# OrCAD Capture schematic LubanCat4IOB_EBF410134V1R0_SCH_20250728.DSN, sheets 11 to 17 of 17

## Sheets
11 14 MIPI CSI PORT: size A3; note: MIPI CSI PORT
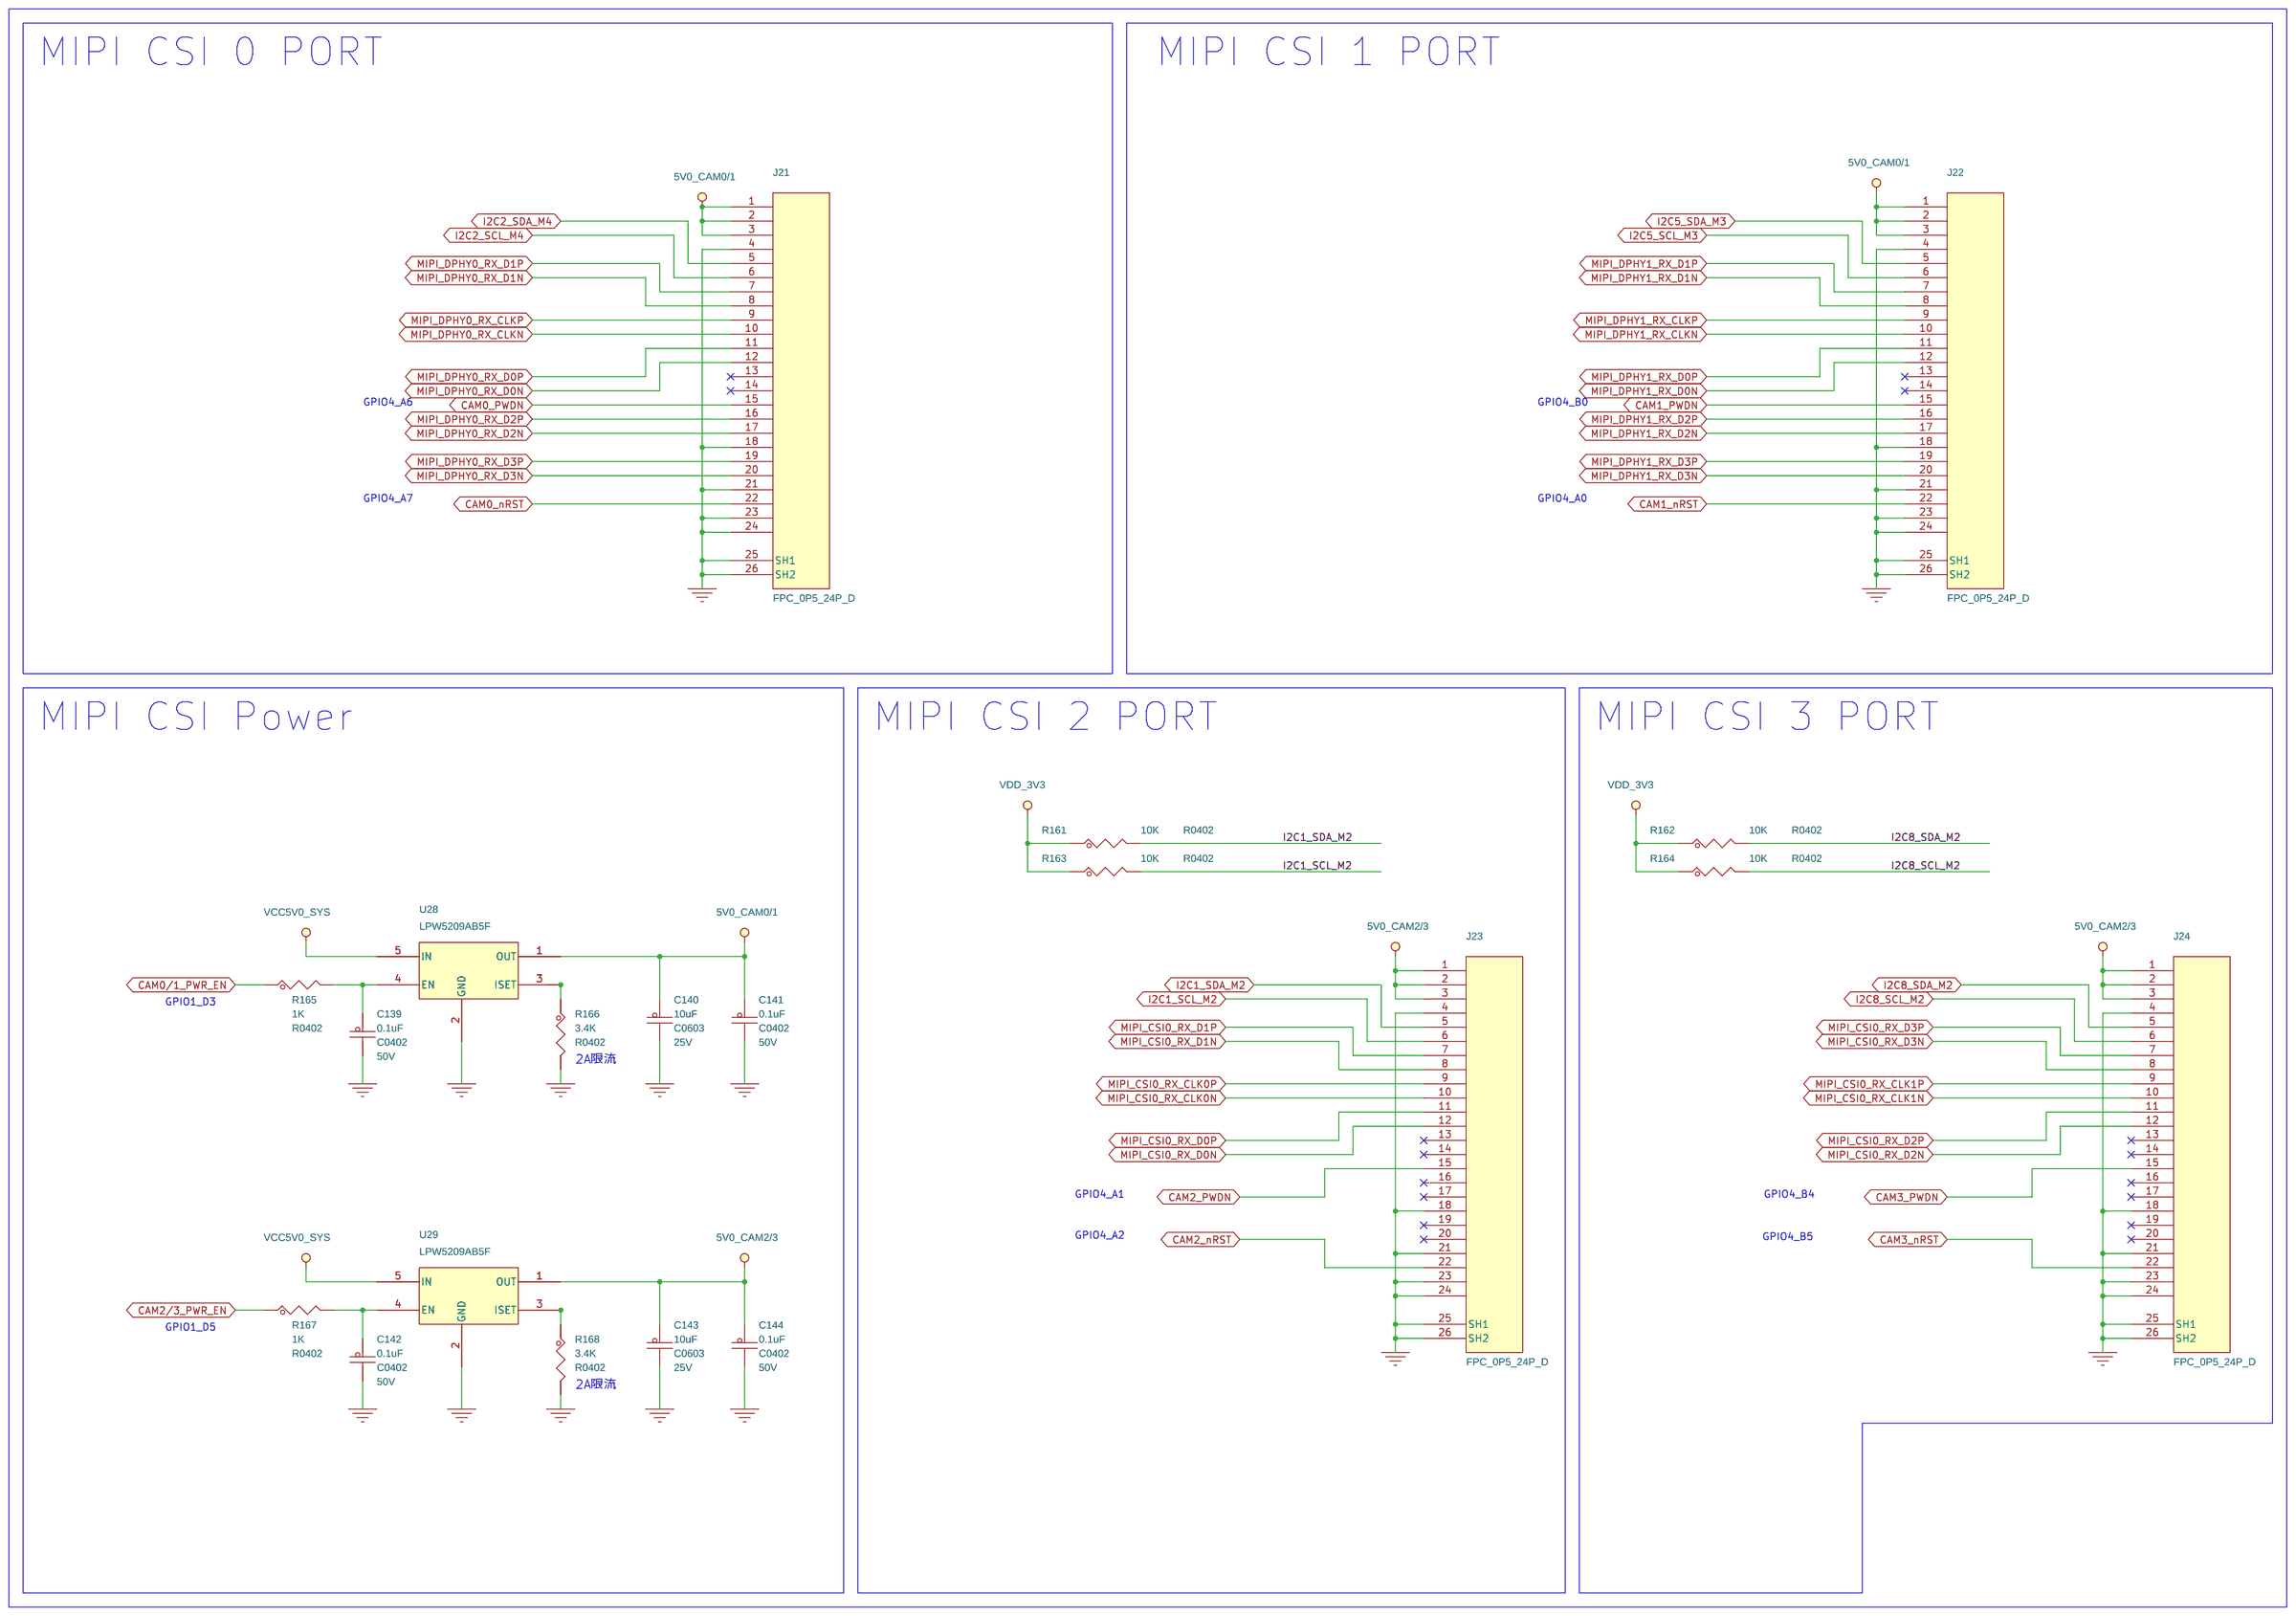
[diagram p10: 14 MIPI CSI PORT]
12 15 MINI PCIE_PORT: size A3; note: MINI PCIE PORT
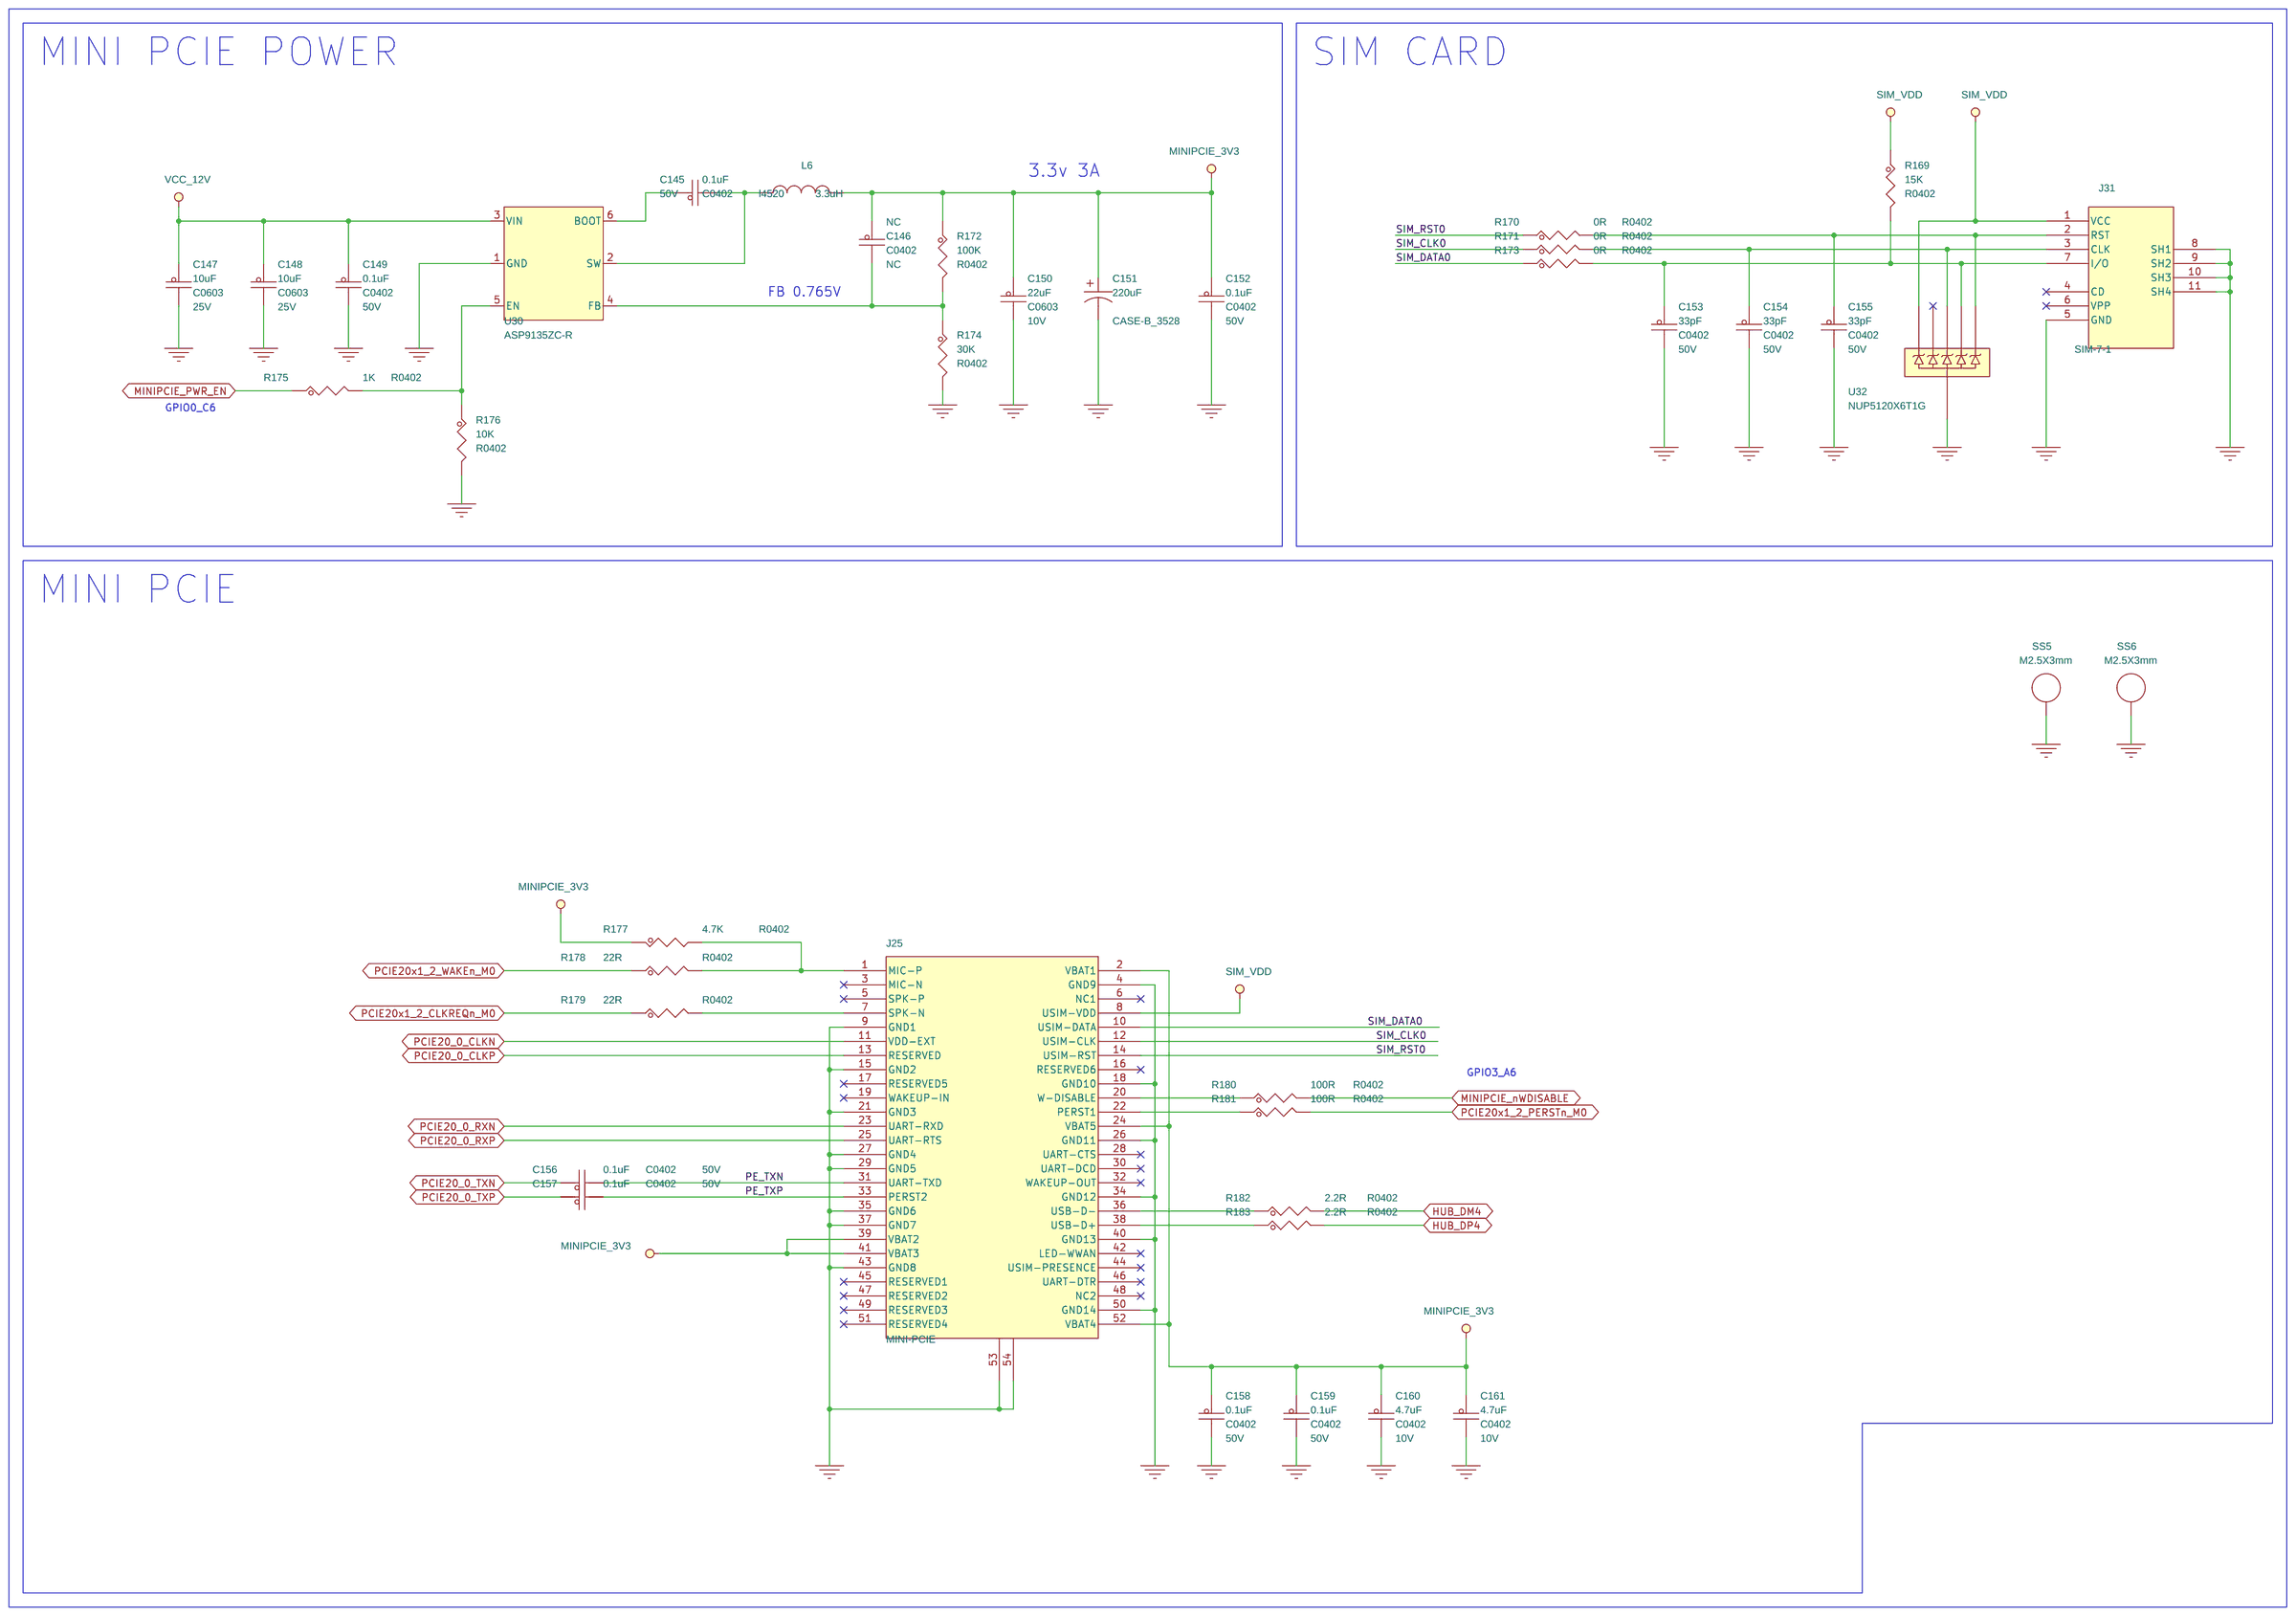
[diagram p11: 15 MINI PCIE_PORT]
13 16 AUDIO PORT: size A3; note: AUDIO PORT
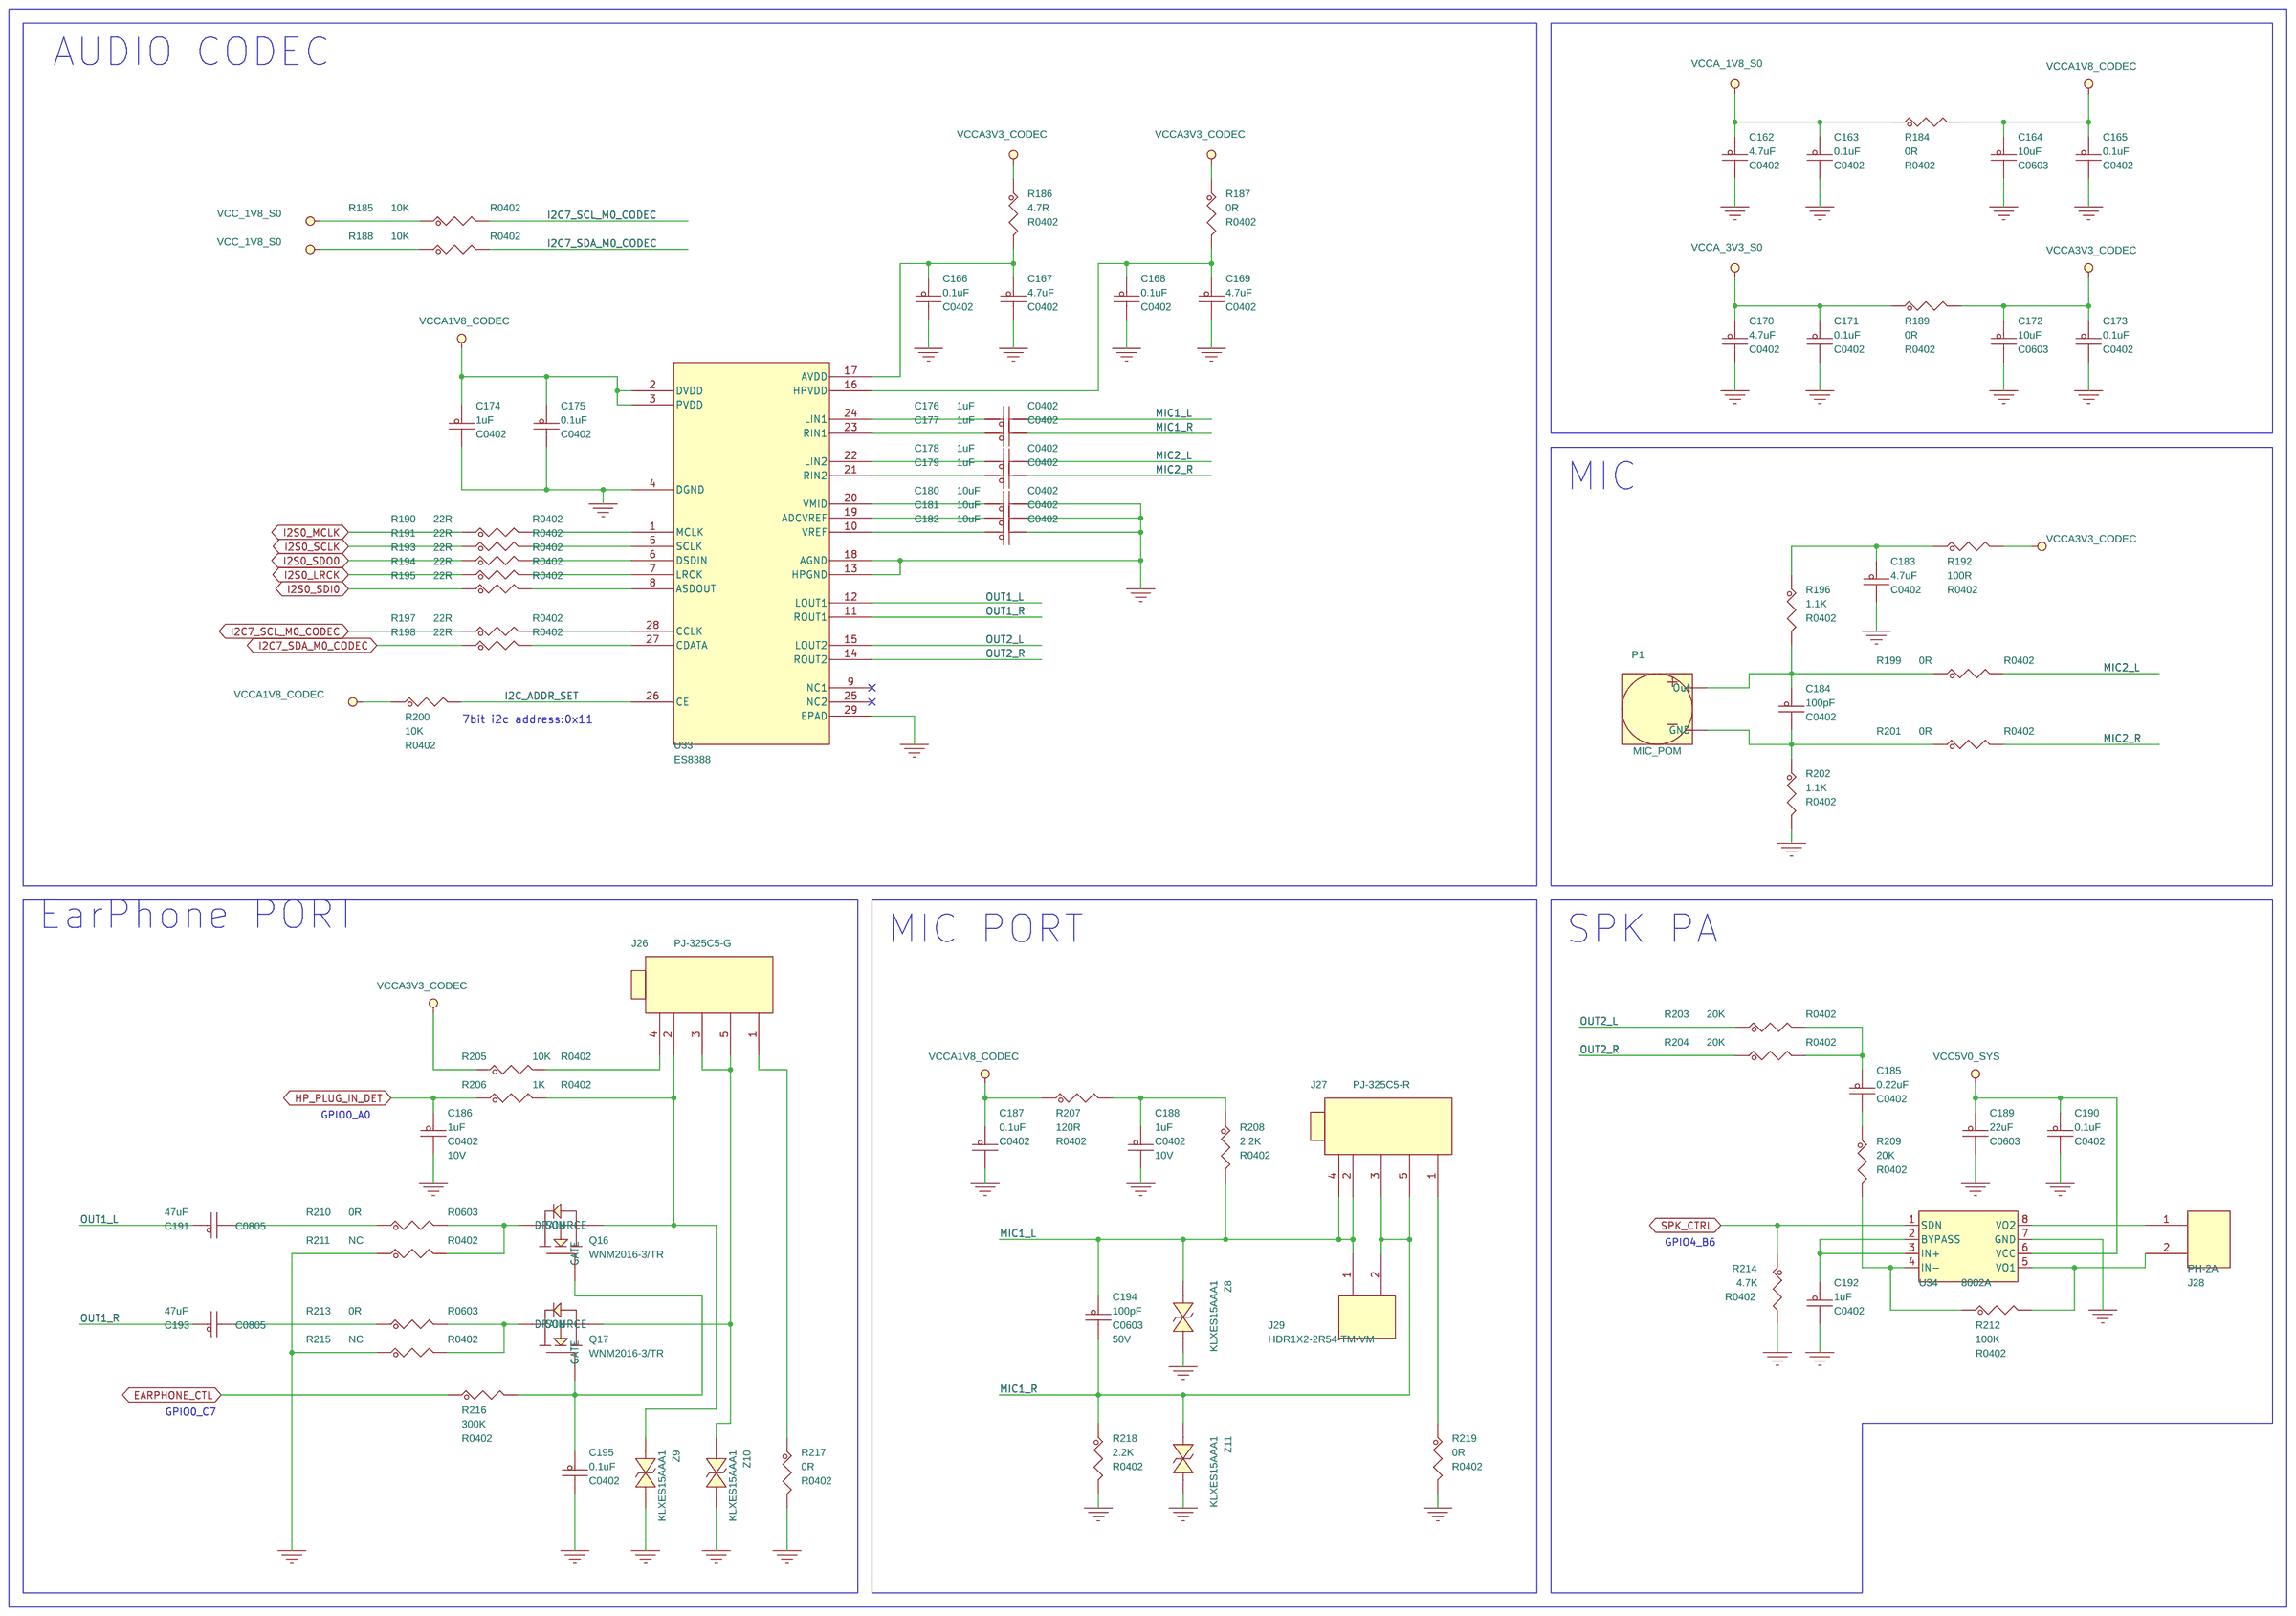
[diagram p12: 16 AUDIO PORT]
14 07 SD/RS232/RTC: size A3; note: RTC/SD/RS232
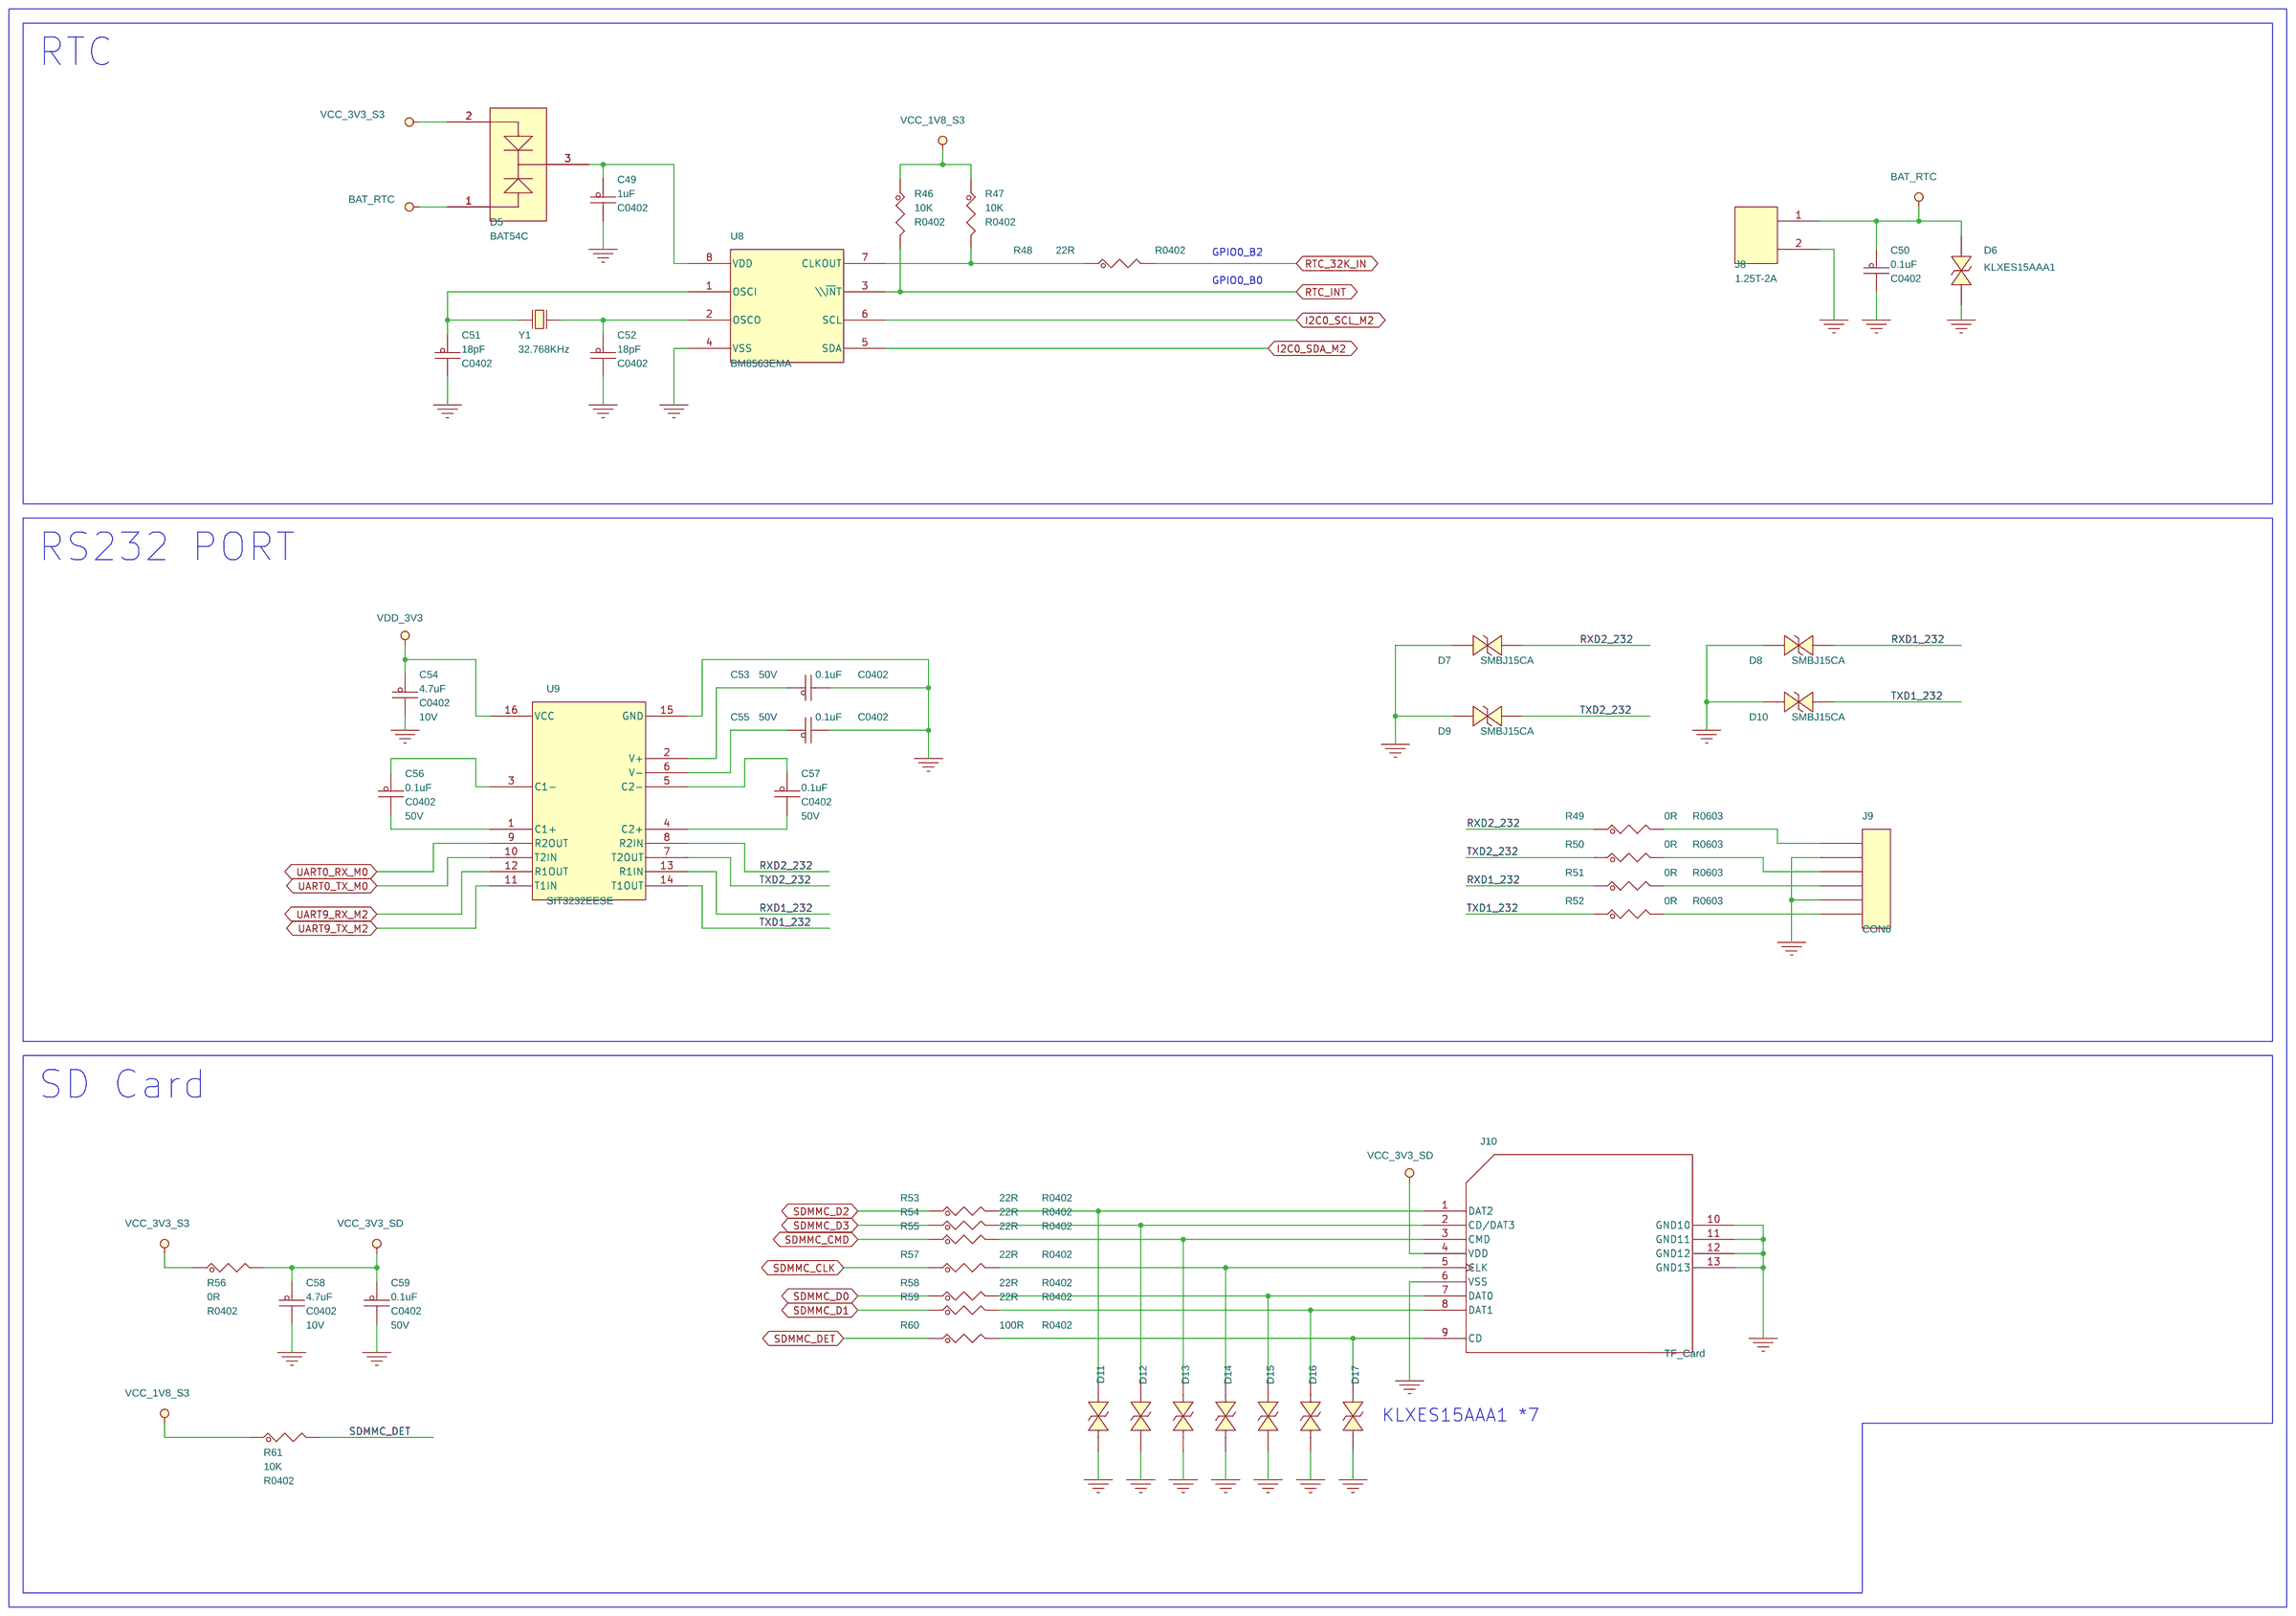
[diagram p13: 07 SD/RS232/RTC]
15 08 RS485/CAN PORT: size A3; note: RS485/CAN PORT
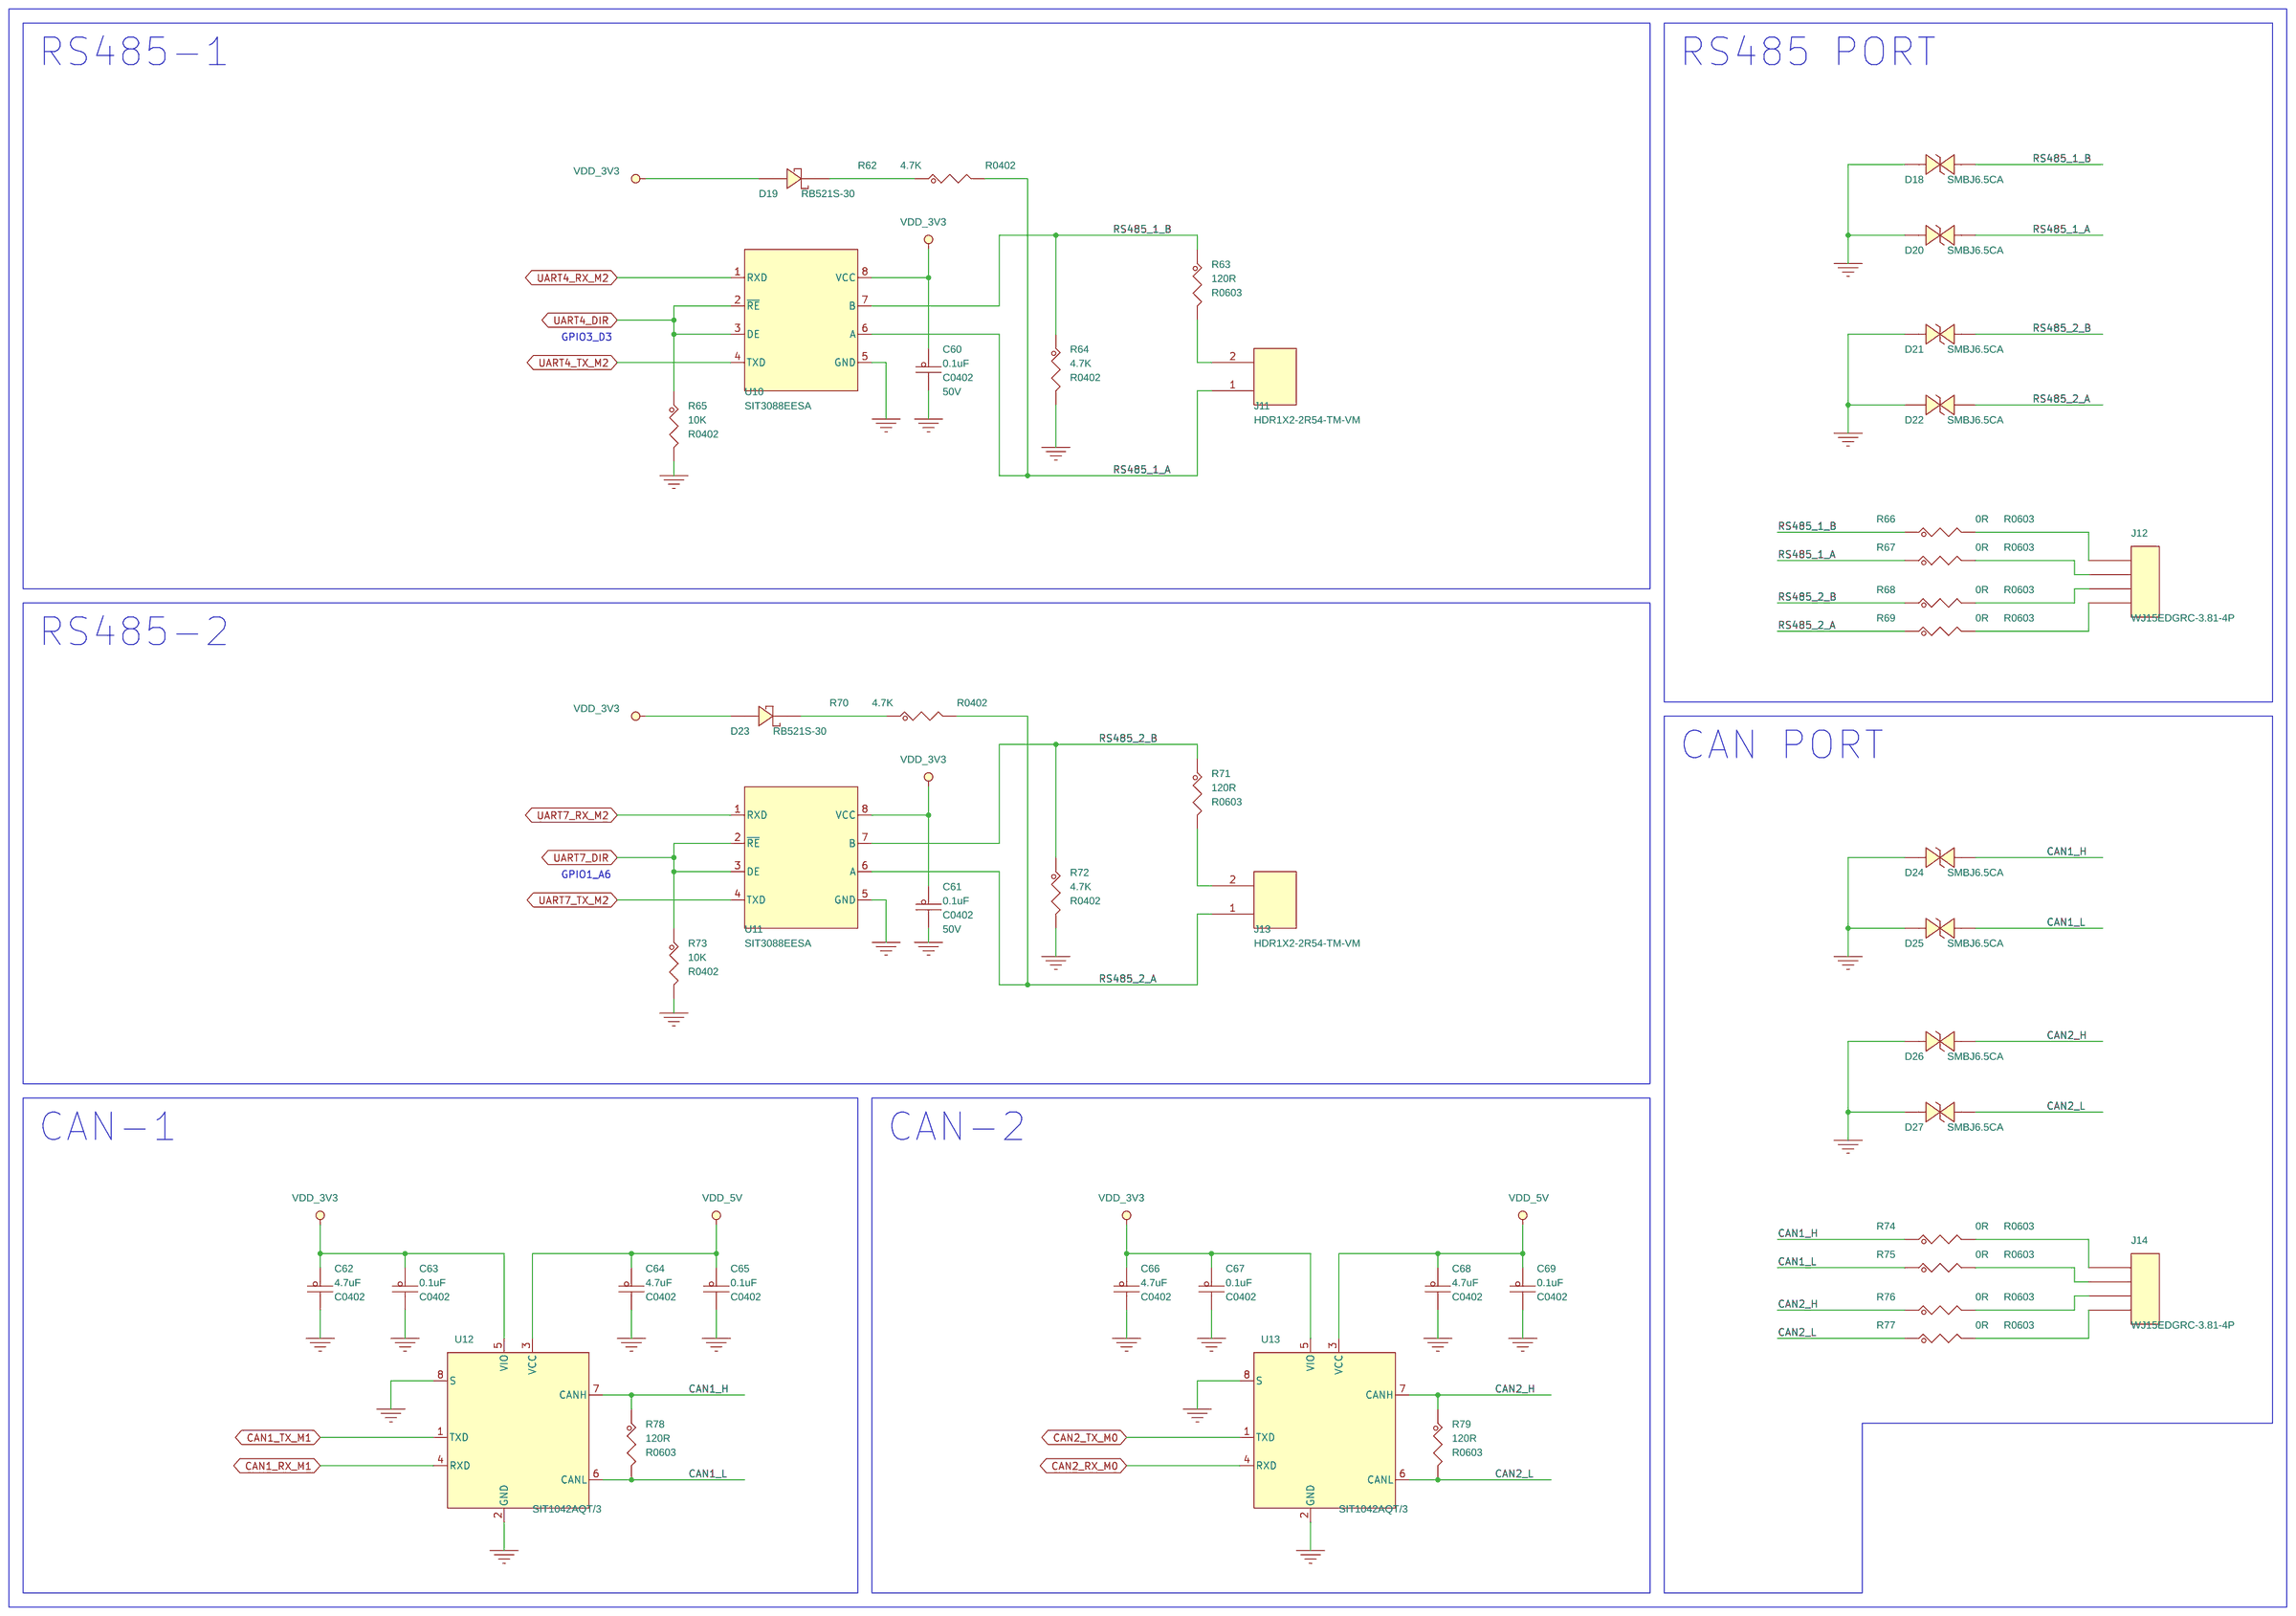
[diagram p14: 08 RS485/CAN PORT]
16 04 DC IN/POWER/FAN: size A3; note: DC IN/POWER/FAN
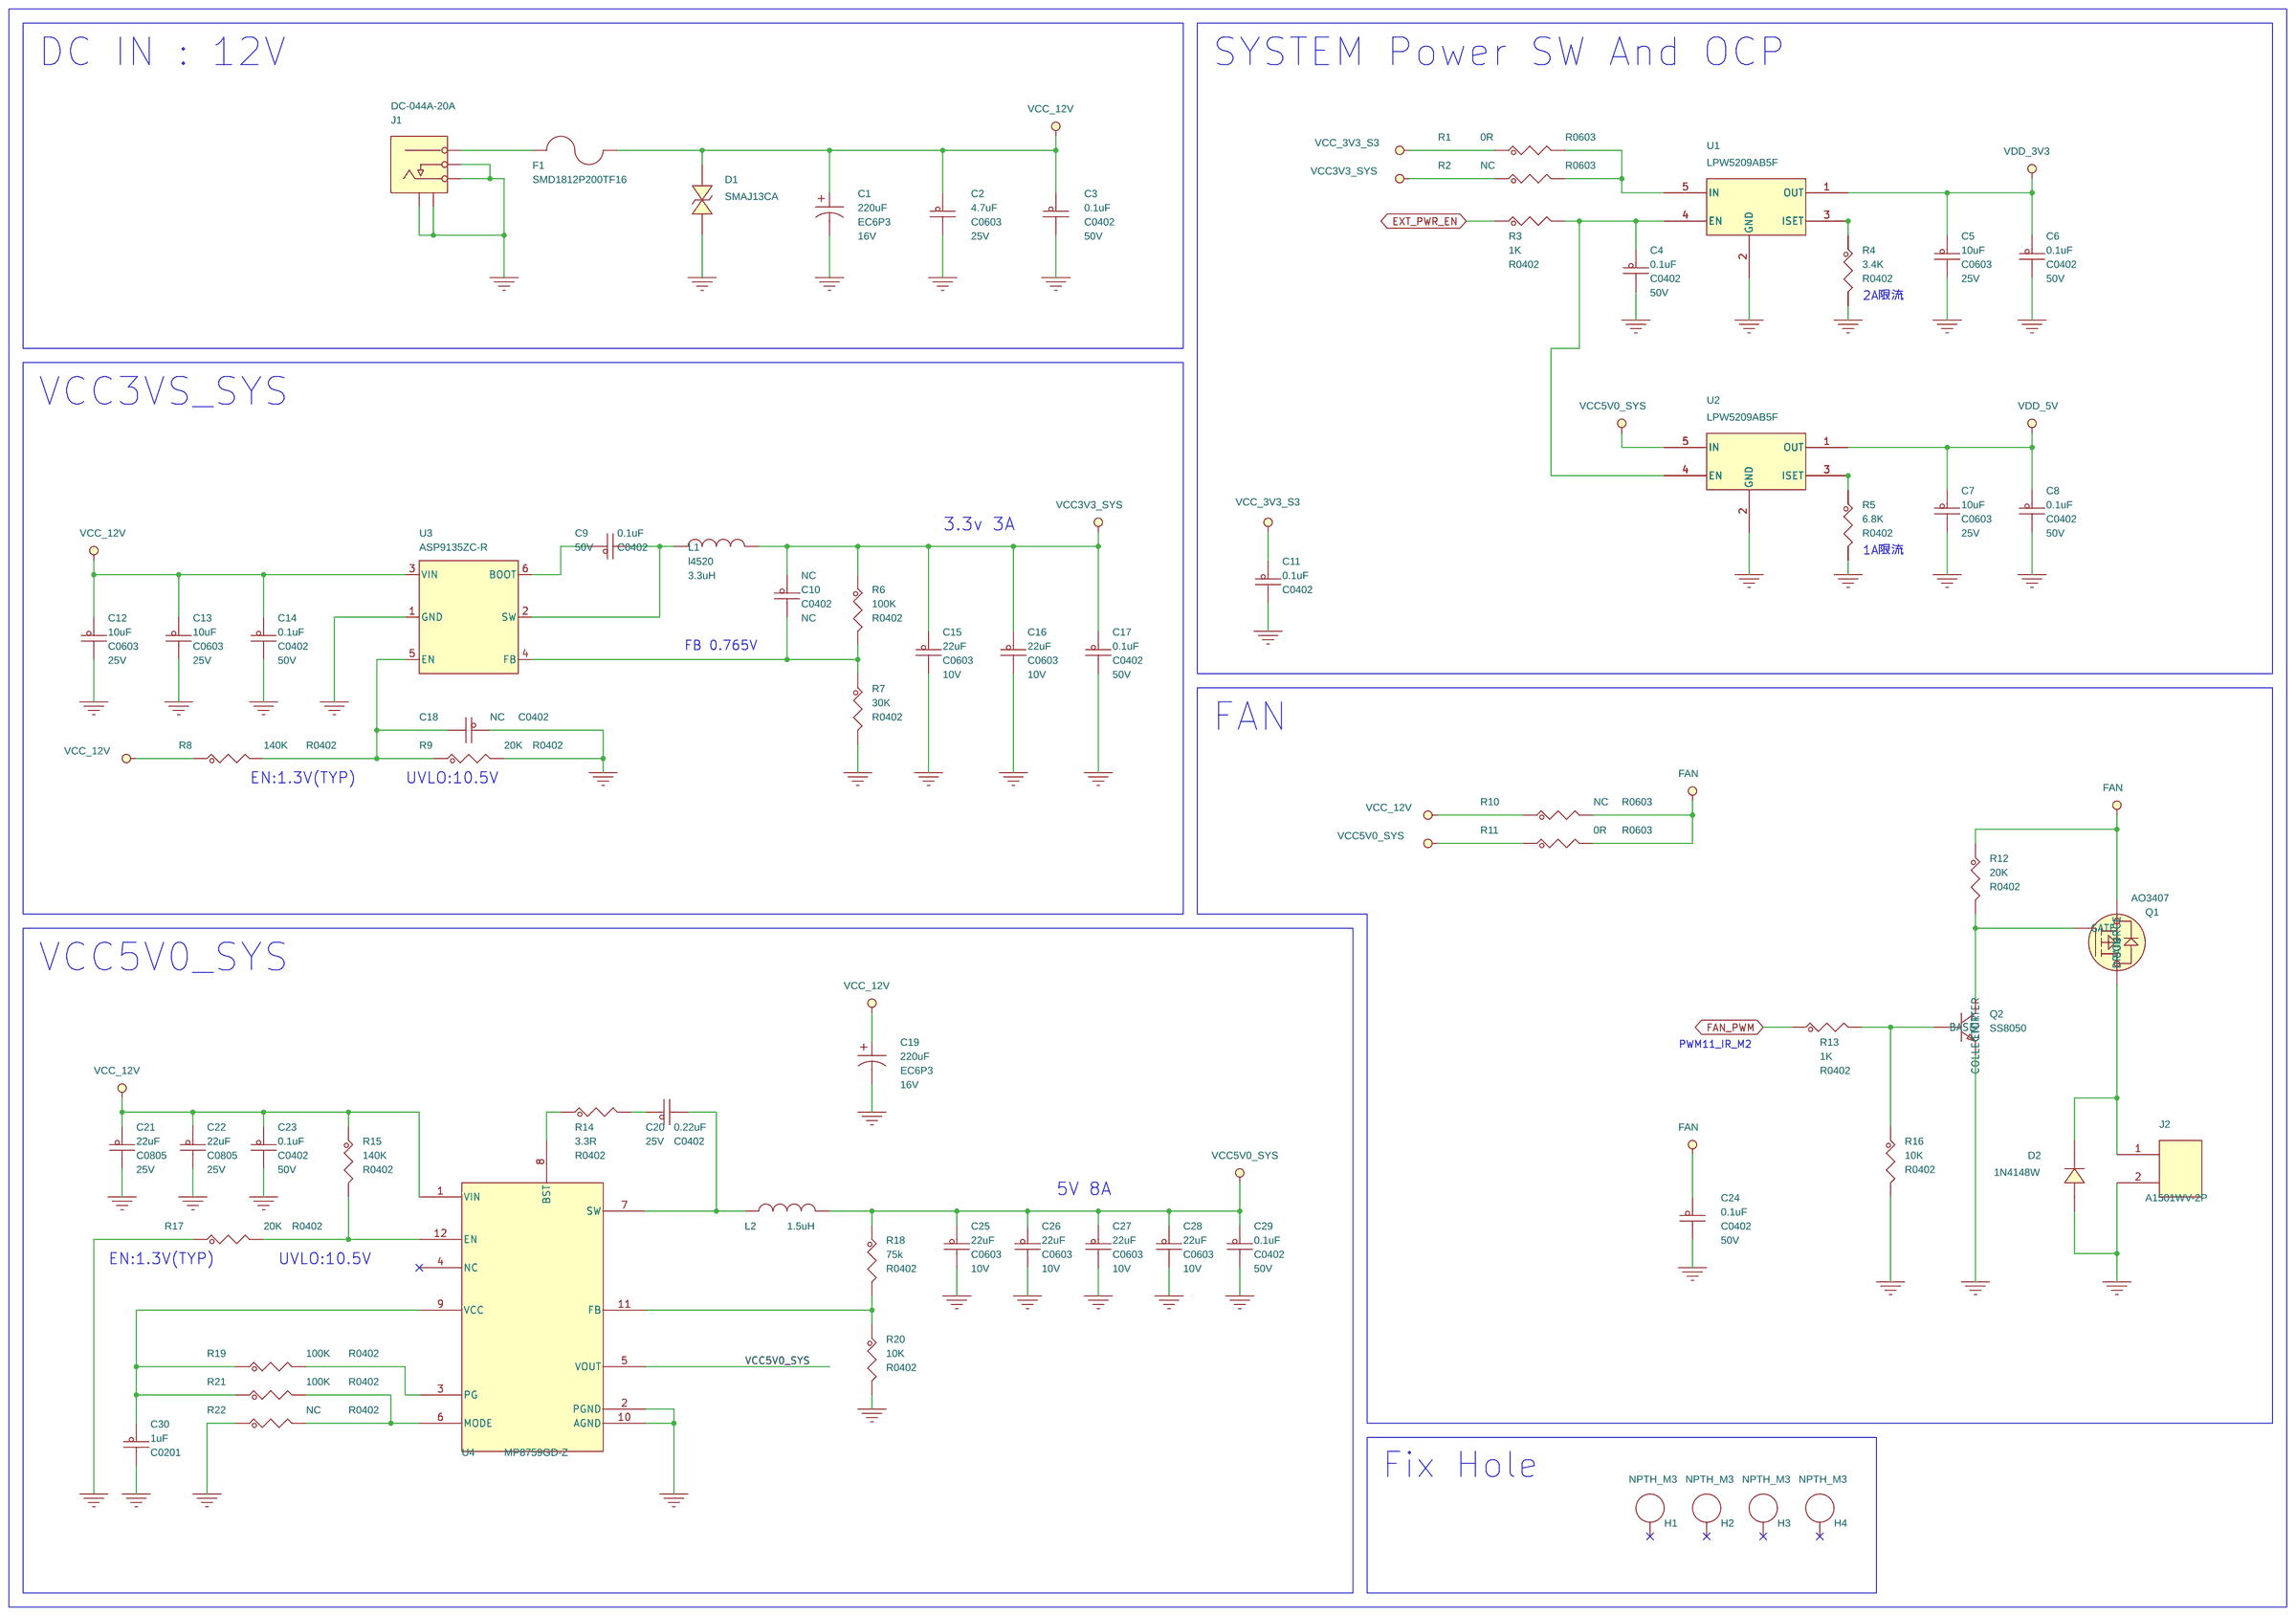
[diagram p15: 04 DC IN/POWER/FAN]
17 06 Button/IR/DEBUG/LED: size A3; note: Button/IR/DEBUG/LED
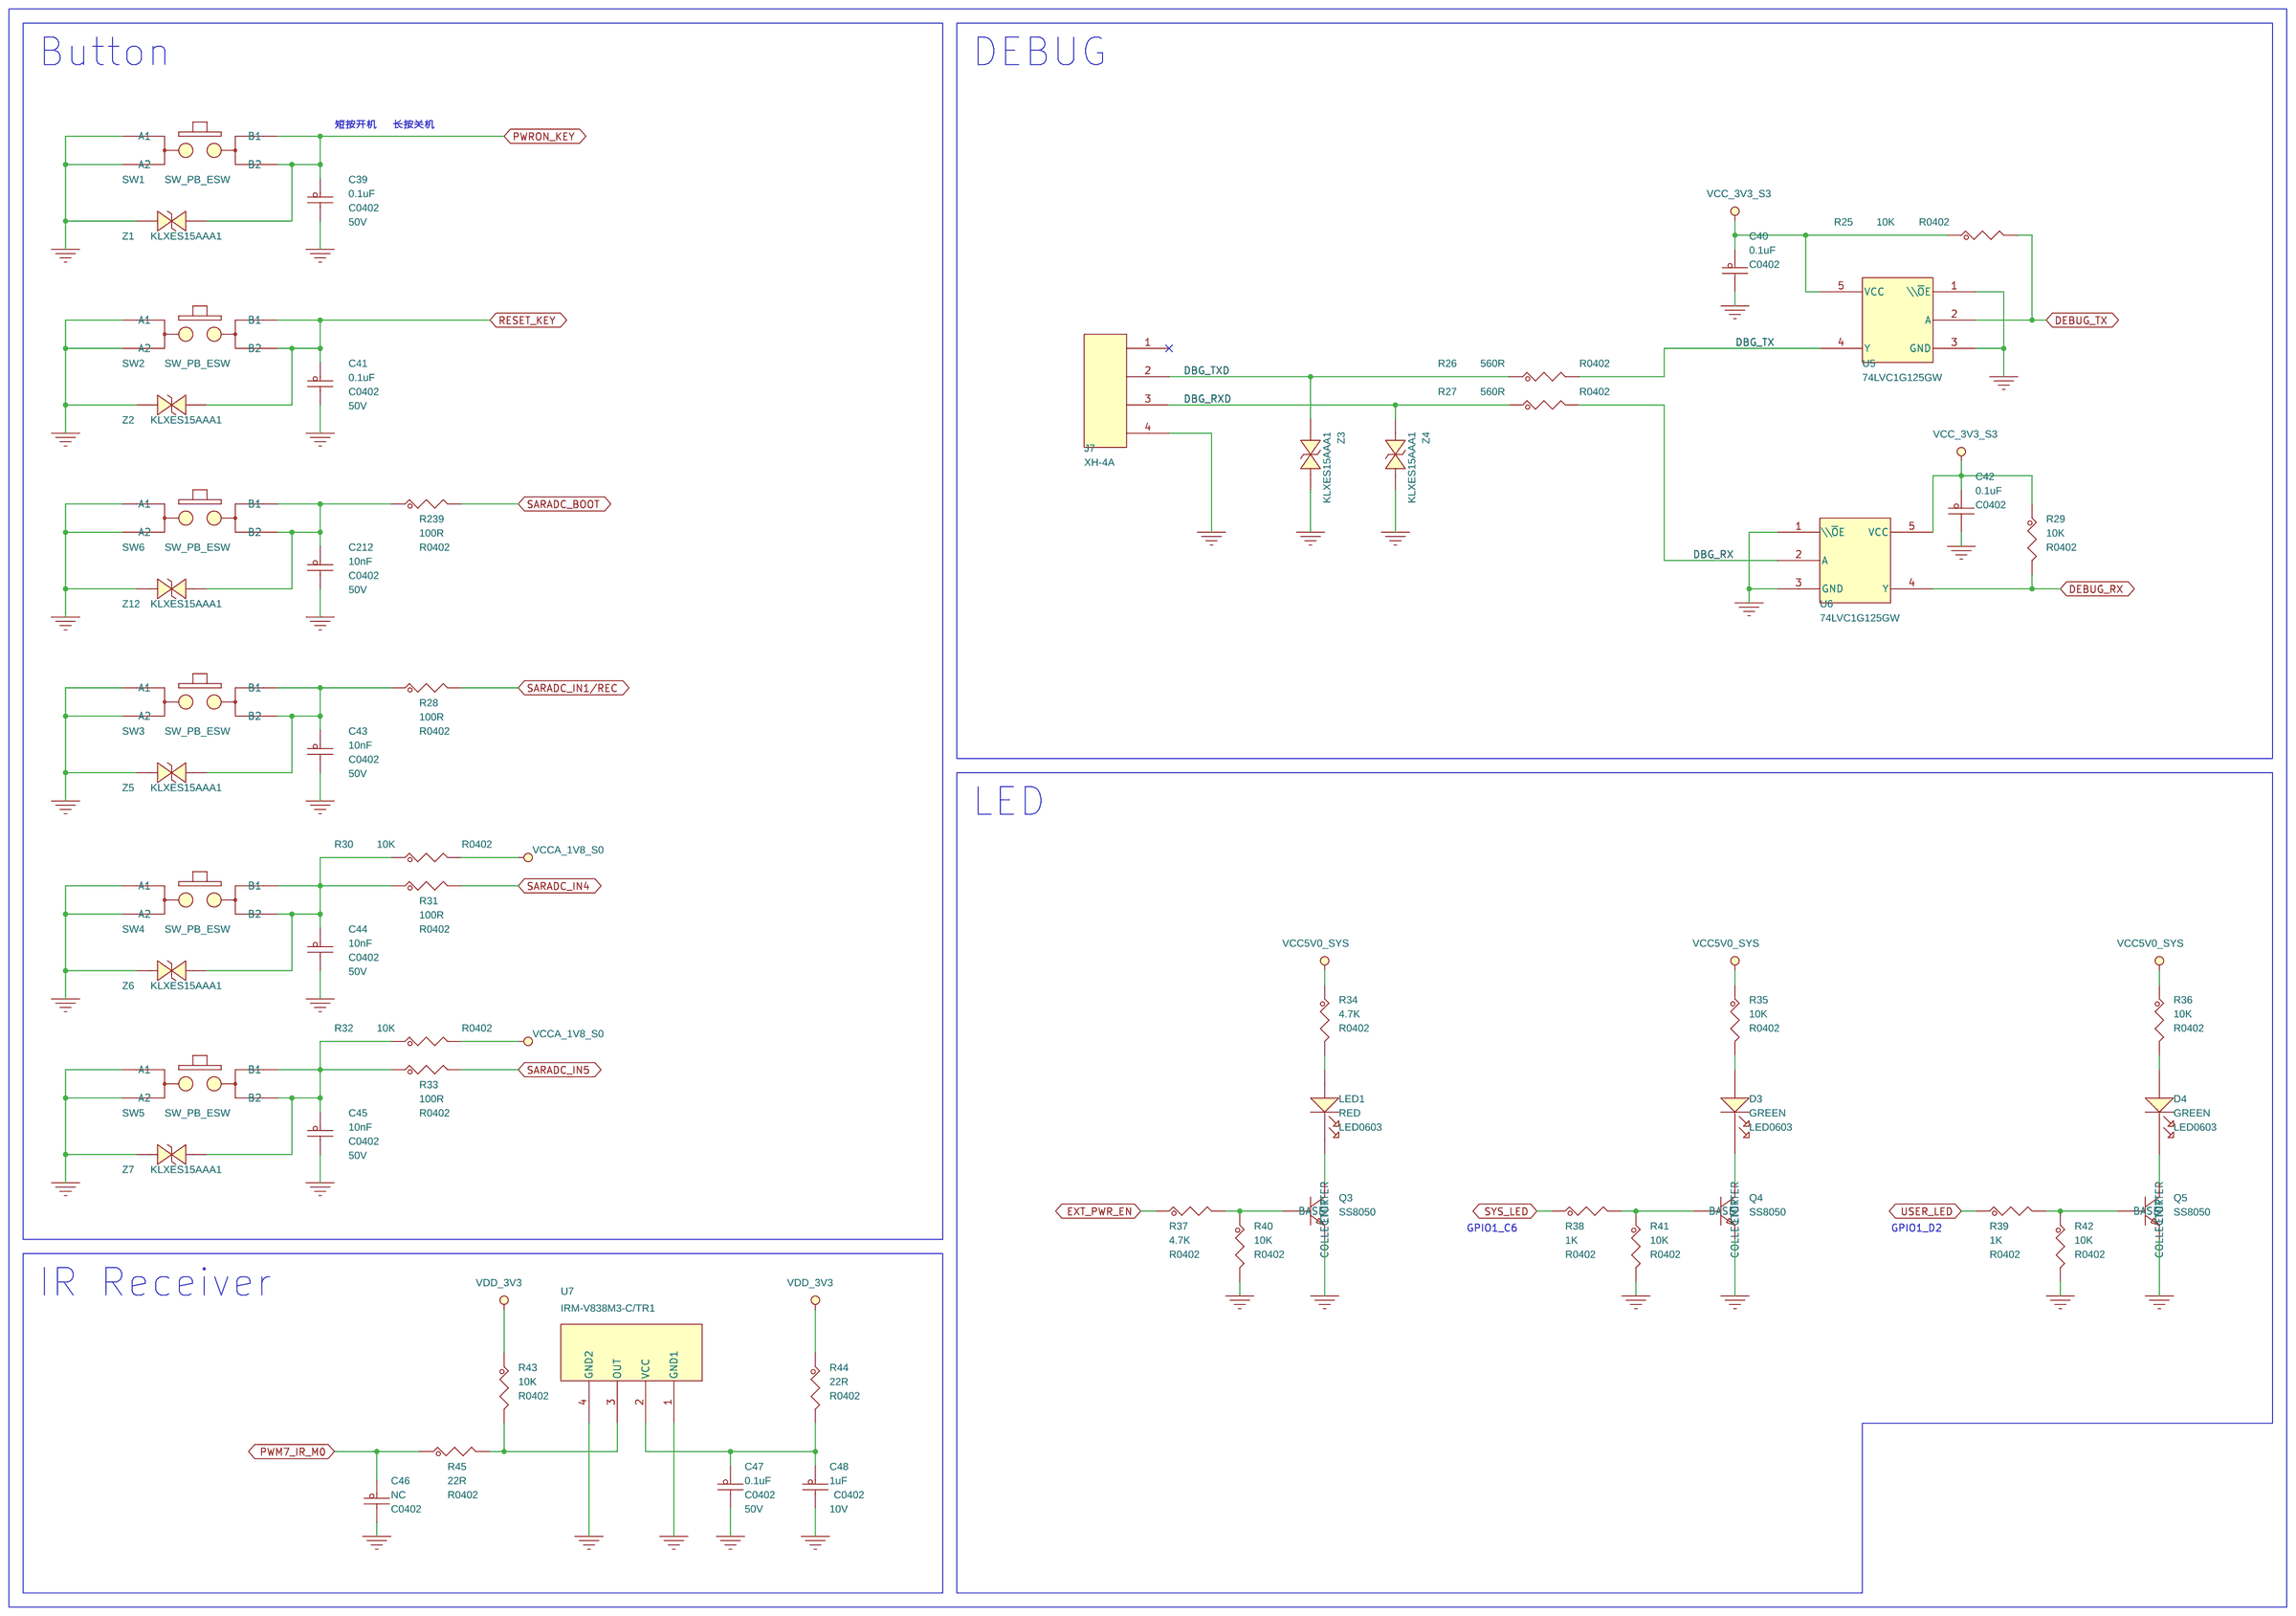
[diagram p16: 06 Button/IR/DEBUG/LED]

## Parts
sheet 04 DC IN/POWER/FAN
C1  220uF  [EC6P3]
C2  4.7uF  [C0603]
C3  0.1uF  [C0402]
C4  0.1uF  [C0402]
C5  10uF  [C0603]
C6  0.1uF  [C0402]
C7  10uF  [C0603]
C8  0.1uF  [C0402]
C9  0.1uF  [C0402]
C10  NC  [C0402]
C11  0.1uF  [C0402]
C12  10uF  [C0603]
C13  10uF  [C0603]
C14  0.1uF  [C0402]
C15  22uF  [C0603]
C16  22uF  [C0603]
C17  0.1uF  [C0402]
C18  NC  [C0402]
C19  220uF  [EC6P3]
C20  0.22uF  [C0402]
C21  22uF  [C0805]
C22  22uF  [C0805]
C23  0.1uF  [C0402]
C24  0.1uF  [C0402]
C25  22uF  [C0603]
C26  22uF  [C0603]
C27  22uF  [C0603]
C28  22uF  [C0603]
C29  0.1uF  [C0402]
C30  1uF  [C0201]
D1  SMAJ13CA  [SMA_CA]
D2  1N4148W  [SOD-123]
F1  SMD1812P200TF16  [F1812]
H1  NPTH_M3  [NPTH_M3]
H2  NPTH_M3  [NPTH_M3]
H3  NPTH_M3  [NPTH_M3]
H4  NPTH_M3  [NPTH_M3]
J1  DC-044A-20A  [dc_in_th_3p_10r1x11r6]
J2  A1501WV-2P  [zh1p5mm_th_2p]
L1  3.3uH  [l4520]
L2  1.5uH  [L0518]
Q1  AO3407  [SOT23]
Q2  SS8050  [SOT23]
R1  0R  [R0603]
R2  NC  [R0603]
R3  1K  [R0402]
R4  3.4K  [R0402]
R5  6.8K  [R0402]
R6  100K  [R0402]
R7  30K  [R0402]
R8  140K  [R0402]
R9  20K  [R0402]
R10  NC  [R0603]
R11  0R  [R0603]
R12  20K  [R0402]
R13  1K  [R0402]
R14  3.3R  [R0402]
R15  140K  [R0402]
R16  10K  [R0402]
R17  20K  [R0402]
R18  75k  [R0402]
R19  100K  [R0402]
R20  10K  [R0402]
R21  100K  [R0402]
R22  NC  [R0402]
U1  LPW5209AB5F  [SOT23-5]
U2  LPW5209AB5F  [SOT23-5]
U3  ASP9135ZC-R  [SOT23_6]
U4  MP8759GD-Z  [QFN12-2R00X3R00]
sheet 06 Button/IR/DEBUG/LED
C39  0.1uF  [C0402]
C40  0.1uF  [C0402]
C41  0.1uF  [C0402]
C42  0.1uF  [C0402]
C43  10nF  [C0402]
C44  10nF  [C0402]
C45  10nF  [C0402]
C46  NC  [C0402]
C47  0.1uF  [C0402]
C48  1uF  [C0402]
C212  10nF  [C0402]
D3  GREEN  [LED0603]
D4  GREEN  [LED0603]
J7  XH-4A  [XH2R54-4P-V]
LED1  RED  [LED0603]
Q3  SS8050  [SOT23]
Q4  SS8050  [SOT23]
Q5  SS8050  [SOT23]
R25  10K  [R0402]
R26  560R  [R0402]
R27  560R  [R0402]
R28  100R  [R0402]
R29  10K  [R0402]
R30  10K  [R0402]
R31  100R  [R0402]
R32  10K  [R0402]
R33  100R  [R0402]
R34  4.7K  [R0402]
R35  10K  [R0402]
R36  10K  [R0402]
R37  4.7K  [R0402]
R38  1K  [R0402]
R39  1K  [R0402]
R40  10K  [R0402]
R41  10K  [R0402]
R42  10K  [R0402]
R43  10K  [R0402]
R44  22R  [R0402]
R45  22R  [R0402]
R239  100R  [R0402]
SW1  SW_PB_ESW  [SW4-4R20X3R25-SM]
SW2  SW_PB_ESW  [SW4-4R20X3R25-SM]
SW3  SW_PB_ESW  [SW4-4R20X3R25-SM]
SW4  SW_PB_ESW  [SW4-4R20X3R25-SM]
SW5  SW_PB_ESW  [SW4-4R20X3R25-SM]
SW6  SW_PB_ESW  [SW4-4R20X3R25-SM]
U5  74LVC1G125GW  [SOT-353]
U6  74LVC1G125GW  [SOT-353]
U7  IRM-V838M3-C/TR1  [SMD4-6R80X2R50]
Z1  KLXES15AAA1  [ES0402]
Z2  KLXES15AAA1  [ES0402]
Z3  KLXES15AAA1  [ES0402]
Z4  KLXES15AAA1  [ES0402]
Z5  KLXES15AAA1  [ES0402]
Z6  KLXES15AAA1  [ES0402]
Z7  KLXES15AAA1  [ES0402]
Z12  KLXES15AAA1  [ES0402]
sheet 07 SD/RS232/RTC
C49  1uF  [C0402]
C50  0.1uF  [C0402]
C51  18pF  [C0402]
C52  18pF  [C0402]
C53  0.1uF  [C0402]
C54  4.7uF  [C0402]
C55  0.1uF  [C0402]
C56  0.1uF  [C0402]
C57  0.1uF  [C0402]
C58  4.7uF  [C0402]
C59  0.1uF  [C0402]
D5  BAT54C  [SOT23]
D6  KLXES15AAA1  [ES0402]
D7  SMBJ15CA  [SMB-CA]
D8  SMBJ15CA  [SMB-CA]
D9  SMBJ15CA  [SMB-CA]
D10  SMBJ15CA  [SMB-CA]
D11  KLXES15AAA1  [ES0402]
D12  KLXES15AAA1  [ES0402]
D13  KLXES15AAA1  [ES0402]
D14  KLXES15AAA1  [ES0402]
D15  KLXES15AAA1  [ES0402]
D16  KLXES15AAA1  [ES0402]
D17  KLXES15AAA1  [ES0402]
J8  1.25T-2A  [gh1p25_th_2p]
J9  CON6  [DB2ERC-3P81-6P]
J10  TF_Card  [TFCARD]
R46  10K  [R0402]
R47  10K  [R0402]
R48  22R  [R0402]
R49  0R  [R0603]
R50  0R  [R0603]
R51  0R  [R0603]
R52  0R  [R0603]
R53  22R  [R0402]
R54  22R  [R0402]
R55  22R  [R0402]
R56  0R  [R0402]
R57  22R  [R0402]
R58  22R  [R0402]
R59  22R  [R0402]
R60  100R  [R0402]
R61  10K  [R0402]
U8  BM8563EMA  [msop-8]
U9  SIT3232EESE  [SOIC16]
Y1  32.768KHz  [3215]
sheet 08 RS485/CAN PORT
C60  0.1uF  [C0402]
C61  0.1uF  [C0402]
C62  4.7uF  [C0402]
C63  0.1uF  [C0402]
C64  4.7uF  [C0402]
C65  0.1uF  [C0402]
C66  4.7uF  [C0402]
C67  0.1uF  [C0402]
C68  4.7uF  [C0402]
C69  0.1uF  [C0402]
D18  SMBJ6.5CA  [SMB-CA]
D19  RB521S-30  [SOD523]
D20  SMBJ6.5CA  [SMB-CA]
D21  SMBJ6.5CA  [SMB-CA]
D22  SMBJ6.5CA  [SMB-CA]
D23  RB521S-30  [SOD523]
D24  SMBJ6.5CA  [SMB-CA]
D25  SMBJ6.5CA  [SMB-CA]
D26  SMBJ6.5CA  [SMB-CA]
D27  SMBJ6.5CA  [SMB-CA]
J11  HDR1X2-2R54-TM-VM  [HDR1X2-2R54-TM-VM]
J12  WJ15EDGRC-3.81-4P  [DB2ERC-3P81-4P]
J13  HDR1X2-2R54-TM-VM  [HDR1X2-2R54-TM-VM]
J14  WJ15EDGRC-3.81-4P  [DB2ERC-3P81-4P]
R62  4.7K  [R0402]
R63  120R  [R0603]
R64  4.7K  [R0402]
R65  10K  [R0402]
R66  0R  [R0603]
R67  0R  [R0603]
R68  0R  [R0603]
R69  0R  [R0603]
R70  4.7K  [R0402]
R71  120R  [R0603]
R72  4.7K  [R0402]
R73  10K  [R0402]
R74  0R  [R0603]
R75  0R  [R0603]
R76  0R  [R0603]
R77  0R  [R0603]
R78  120R  [R0603]
R79  120R  [R0603]
U10  SIT3088EESA  [SOP8]
U11  SIT3088EESA  [SOP8]
U12  SIT1042AQT/3  [SOP8]
U13  SIT1042AQT/3  [SOP8]
sheet 14 MIPI CSI PORT
C139  0.1uF  [C0402]
C140  10uF  [C0603]
C141  0.1uF  [C0402]
C142  0.1uF  [C0402]
C143  10uF  [C0603]
C144  0.1uF  [C0402]
J21  FPC_0P5_24P_D  [fpc_24p_0p5]
J22  FPC_0P5_24P_D  [fpc_24p_0p5]
J23  FPC_0P5_24P_D  [fpc_24p_0p5]
J24  FPC_0P5_24P_D  [fpc_24p_0p5]
R161  10K  [R0402]
R162  10K  [R0402]
R163  10K  [R0402]
R164  10K  [R0402]
R165  1K  [R0402]
R166  3.4K  [R0402]
R167  1K  [R0402]
R168  3.4K  [R0402]
U28  LPW5209AB5F  [SOT23-5]
U29  LPW5209AB5F  [SOT23-5]
sheet 15 MINI PCIE_PORT
C145  0.1uF  [C0402]
C146  NC  [C0402]
C147  10uF  [C0603]
C148  10uF  [C0603]
C149  0.1uF  [C0402]
C150  22uF  [C0603]
C151  220uF  [CASE-B_3528]
C152  0.1uF  [C0402]
C153  33pF  [C0402]
C154  33pF  [C0402]
C155  33pF  [C0402]
C156  0.1uF  [C0402]
C157  0.1uF  [C0402]
C158  0.1uF  [C0402]
C159  0.1uF  [C0402]
C160  4.7uF  [C0402]
C161  4.7uF  [C0402]
J25  MINI-PCIE  [pcie_52p]
J31  SIM-7-1  [nano_sim]
L6  3.3uH  [l4520]
R169  15K  [R0402]
R170  0R  [R0402]
R171  0R  [R0402]
R172  100K  [R0402]
R173  0R  [R0402]
R174  30K  [R0402]
R175  1K  [R0402]
R176  10K  [R0402]
R177  4.7K  [R0402]
R178  22R  [R0402]
R179  22R  [R0402]
R180  100R  [R0402]
R181  100R  [R0402]
R182  2.2R  [R0402]
R183  2.2R  [R0402]
SS5  M2.5X3mm  [SMTSO-M2r5]
SS6  M2.5X3mm  [SMTSO-M2r5]
U30  ASP9135ZC-R  [SOT23_6]
U32  NUP5120X6T1G  [SOT563]
sheet 16 AUDIO PORT
C162  4.7uF  [C0402]
C163  0.1uF  [C0402]
C164  10uF  [C0603]
C165  0.1uF  [C0402]
C166  0.1uF  [C0402]
C167  4.7uF  [C0402]
C168  0.1uF  [C0402]
C169  4.7uF  [C0402]
C170  4.7uF  [C0402]
C171  0.1uF  [C0402]
C172  10uF  [C0603]
C173  0.1uF  [C0402]
C174  1uF  [C0402]
C175  0.1uF  [C0402]
C176  1uF  [C0402]
C177  1uF  [C0402]
C178  1uF  [C0402]
C179  1uF  [C0402]
C180  10uF  [C0402]
C181  10uF  [C0402]
C182  10uF  [C0402]
C183  4.7uF  [C0402]
C184  100pF  [C0402]
C185  0.22uF  [C0402]
C186  1uF  [C0402]
C187  0.1uF  [C0402]
C188  1uF  [C0402]
C189  22uF  [C0603]
C190  0.1uF  [C0402]
C191  47uF  [C0805]
C192  1uF  [C0402]
C193  47uF  [C0805]
C194  100pF  [C0603]
C195  0.1uF  [C0402]
J26  PJ-325C5-G  [EAR_JACK]
J27  PJ-325C5-R  [EAR_JACK]
J28  PH-2A  [PH-1x2-2P0_l]
J29  HDR1X2-2R54-TM-VM  [HDR1X2-2R54-TM-VM]
P1  MIC_POM  [MIC2-4R00-TM]
Q16  WNM2016-3/TR  [SOT23]
Q17  WNM2016-3/TR  [SOT23]
R184  0R  [R0402]
R185  10K  [R0402]
R186  4.7R  [R0402]
R187  0R  [R0402]
R188  10K  [R0402]
R189  0R  [R0402]
R190  22R  [R0402]
R191  22R  [R0402]
R192  100R  [R0402]
R193  22R  [R0402]
R194  22R  [R0402]
R195  22R  [R0402]
R196  1.1K  [R0402]
R197  22R  [R0402]
R198  22R  [R0402]
R199  0R  [R0402]
R200  10K  [R0402]
R201  0R  [R0402]
R202  1.1K  [R0402]
R203  20K  [R0402]
R204  20K  [R0402]
R205  10K  [R0402]
R206  1K  [R0402]
R207  120R  [R0402]
R208  2.2K  [R0402]
R209  20K  [R0402]
R210  0R  [R0603]
R211  NC  [R0402]
R212  100K  [R0402]
R213  0R  [R0603]
R214  4.7K  [R0402]
R215  NC  [R0402]
R216  300K  [R0402]
R217  0R  [R0402]
R218  2.2K  [R0402]
R219  0R  [R0402]
U33  ES8388  [qfn28_0r45-4x4EP2R6X2R6]
U34  8002A  [SOP8]
Z8  KLXES15AAA1  [ES0402]
Z9  KLXES15AAA1  [ES0402]
Z10  KLXES15AAA1  [ES0402]
Z11  KLXES15AAA1  [ES0402]

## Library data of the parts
C1 C19 = CAP: Voltage: 16V; 规格: 贴片电解电容220uF 20% 16V 尺寸6.3mmX5.8mm 工作寿命：2000H@105℃; 规格编号: VZT221M1CTR-0606ACS; 规格书: 台湾立隆-贴片型铝电解电容.pdf; 价格: 0.566564; 类别: 贴片型铝电解电容; 品牌: 台湾立隆; 生命周期: 量产; 条码: EBF29060148
C2 = CAP_NP: Voltage: 25V; 规格: 贴片电容4.7uF 10% 25V X7R 0603; 规格编号: CL10A475KA8NQNC; 规格书: 三星电容.pdf; 价格: 0.031274; 类别: 贴片电容0603; 品牌: 三星; 生命周期: 量产; 条码: EBF29060162
C3 C4 C6 C8 C9 C14 C17 C23 C24 C29 C39 C41 C47 C53 C55-C57 C59-C61 C139 C141 C142 C144 C145 C149 C152 C156-C159 = CAP_NP: Voltage: 50V; 规格: 贴片电容0.1uF 10% 50V X5R 0402; 规格编号: 0402X104K500NT; 规格书: 风华电容.pdf; 价格: 0.029826; 类别: 贴片电容0402; 品牌: 风华; 生命周期: 量产; 条码: EBF29060118
C5 C7 C12 C13 C140 C143 C147 C148 = CAP_NP: Voltage: 25V; 规格: 贴片电容10uF 20% 25V X5R 0603; 规格编号: CL10A106MA8NRNC; 规格书: 三星电容.pdf; 价格: 0.109811; 类别: 贴片电容0603; 品牌: 三星; 生命周期: 量产; 条码: EBF29060171
C10 C18 C46 C146 = CAP_NP: 规格: 贴片电容NC 预留; 类别: 贴片电容0402; 条码: EBF29060149
C11 C40 C42 C50 C63 C65 C67 C69 C163 C165 C166 C168 C171 C173 C175 C187 C190 C195 = CAP_NP: voltage: 50V; 规格: 贴片电容0.1uF 10% 50V X5R 0402; 规格编号: 0402X104K500NT; 规格书: 风华电容.pdf; 价格: 0.029826; 类别: 贴片电容0402; 品牌: 风华; 生命周期: 量产; 条码: EBF29060118
C15 C16 C25-C28 C150 = CAP_NP: Voltage: 10V; 规格: 贴片电容22uF 20% 10V X5R 0603; 规格编号: CL10A226MP8NUNE; 规格书: 三星电容.pdf; 价格: 0.078818; 类别: 贴片电容0603; 品牌: 三星; 生命周期: 量产; 条码: EBF29060163
C20 = CAP_NP: Voltage: 25V; 备注: 新增0402物料; 规格: 贴片电容0.22uF 20% 25V X7R 0402; 规格编号: TCC0402X7R224K250AT; 规格书: CCTC_TCC0402X5R105K6R3AT; 价格: 0.0073; 类别: 贴片电容0402; 品牌: CCTC; 生命周期: 量产; 条码: EBFCIS241220094109
C21 C22 = CAP_NP: Voltage: 25V; 规格: 贴片电容22uF 20% 25V X5R 0805; 规格编号: 0805X226M250NT; 规格书: 风华电容.pdf; 价格: 0.285631; 类别: 贴片电容0805; 品牌: 风华; 生命周期: 量产; 条码: EBF29060173
C30 = CAP_NP: voltage: 10V; 规格: 贴片电容1uF 20% 10V X5R 0201; 规格编号: GRM033R61A105M; 规格书: 村田0201系列贴片电容.pdf; 价格: 0.036418; 类别: 贴片电容0201; 品牌: 村田; 生命周期: 量产; 条码: EBF29060299
D1 = DIODE_BI-DIR_TRIG: 规格: TVS二极管 箝位电压21.5V 击穿电压14.4V 反向关断电压13V; 规格书: 伯恩半导体-SMAJ13CA.pdf; 价格: 0.181964; 类别: 贴片TVS; 品牌: 伯恩半导体; 生命周期: 量产; 条码: EBF29140049
D2 = DIODE: 规格: 开关二极管 反向耐压值100V 平均整流电流150mA 正向压降1.25V 150mA 功率500mW; 规格书: 1N4148WT4.pdf; 价格: 0.061637; 类别: 贴片开关二极管; 品牌: 江苏长电; 生命周期: 量产; 丝印: T4; 条码: EBF29140015
F1 = FUSE: 规格: 自恢复保险丝 最大电压46V 最大电流100A 保持电流2A 跳闸电流4A; 规格书: 瑞隆源-自恢复保险丝.pdf; 价格: 0.385618; 类别: 自恢复保险丝; 品牌: 瑞隆源; 生命周期: 量产; 条码: EBF29270006
H1-H4 = SPACER: 规格编号: M3螺丝孔_无铜; 类别: M3螺丝孔; 品牌: 野火; 生命周期: 量产; 条码: EBFCIS220926102704
J1 = DC-044A-20A: 规格: DC-044A-20A DC插座; 规格编号: DC-044A-20A DC; 规格书: DC插座_内径_2MM外径_5.9MM.pdf; 类别: DC电源座; 生命周期: 量产; 条码: EBF29040093
J2 = 1X2PIN: 规格: ZH1.5直插 镀锡 2P 针座连接器; 规格书: 长江连接器_A1501WV-2P.PDF; 类别: 线对板连接器; 品牌: 长江连接器; 生命周期: 量产; 条码: EBF29040095
L1 L6 = IND: 规格: 贴片电感3.3uH ±20% 3A 直流电阻69mΩ; 规格编号: TMPC0402HP-3R3MG-Z02; 规格书: 台庆-功率电感.pdf; 价格: 1.5992; 类别: 贴片电感0402; 品牌: 台庆; 生命周期: 量产; 条码: EBF29050040
L2 = IND: 规格: 贴片电感1.5uH ±20% 7.5A 直流电阻25mΩ; 规格编号: FXL0518-1R5-M; 规格书: 长江微电_FXL0518-1R5-M.pdf; 价格: 0.525895; 类别: 贴片电感SMD; 品牌: 长江微电; 生命周期: 量产; 条码: EBFCIS221116170516
Q1 = MOSFET_P: 规格: P沟道MOS 导通电阻60mΩ 电流4.1A 3V可驱动; 规格书: 合科泰-AO3407.pdf; 价格: 0.199827; 类别: P-MOS; 品牌: 合科泰; 生命周期: 量产; 丝印: A7; 条码: EBF29280012
Q2-Q5 = NPN: 规格: 贴片三极管SS8050 集电极电流1.5A 额定功率300mW NPN; 规格书: 江苏长电-SS8050Y1.pdf; 价格: 0.086744; 类别: 贴片三极管SOT-23; 品牌: 江苏长电; 生命周期: 量产; 丝印: Y1; 条码: EBF29090001
R1 R11 R49-R52 R66-R69 R74-R77 R210 R213 = RES: 规格: 贴片电阻0R 1% 1/10W 0603; 规格编号: RI0603L0000FT; 规格书: 合科泰-RI系列电阻.pdf; 类别: 贴片电阻0603; 品牌: 合科泰; 生命周期: 量产; 条码: EBF29070063
R2 R10 = RES: 规格: 贴片电阻NC 预留; 类别: 贴片电阻0603; 条码: EBF29070088
R3 R13 R38 R39 R165 R167 R175 R206 = RES: 规格: 贴片电阻1K 1% 1/16W 0402; 规格编号: RI0402L1001FT; 规格书: 合科泰-RI系列电阻.pdf; 类别: 贴片电阻0402; 品牌: 合科泰; 生命周期: 量产; 条码: EBF29070050
R4 R166 R168 = RES: 规格: 贴片电阻3.4K 1% 1/16W 0402; 规格编号: RI0402L3401FT; 规格书: 合科泰-RI系列电阻.pdf; 类别: 贴片电阻0402; 品牌: 合科泰; 生命周期: 量产; 条码: EBF29070186
R5 = RES: 规格: 贴片电阻6.8K 1% 1/16W 0402; 规格编号: RI0402L6801FT; 规格书: 合科泰-RI系列电阻.pdf; 类别: 贴片电阻0402; 品牌: 合科泰; 生命周期: 量产; 条码: EBF29070052
R6 R19 R21 R172 R212 = RES: 规格: 贴片电阻100K 1% 1/16W 0402; 规格编号: RI0402L1003FT; 规格书: 合科泰-RI系列电阻.pdf; 类别: 贴片电阻0402; 品牌: 合科泰; 生命周期: 量产; 条码: EBF29070054
R7 R174 = RES: 规格: 贴片电阻30K 1% 1/16W 0402; 规格编号: RI0402L3002FT; 规格书: 合科泰-RI系列电阻.pdf; 类别: 贴片电阻0402; 品牌: 合科泰; 生命周期: 量产; 条码: EBF29070048
R8 R15 = RES: 规格: 贴片电阻140K 1% 1/16W 0402; 规格编号: RI0402L1403FT; 规格书: 合科泰-RI系列电阻.pdf; 类别: 贴片电阻0402; 品牌: 合科泰; 生命周期: 量产; 条码: EBF29070058
R9 R12 R17 R203 R204 R209 = RES: 规格: 贴片电阻20K 1% 1/16W 0402; 规格编号: 0402WGF2002TCE; 规格书: 厚声-无铅厚膜电阻.pdf; 价格: 0.002473; 类别: 贴片电阻0402; 品牌: 厚声; 生命周期: 量产; 条码: EBF29070223
R14 = RES: 规格: 贴片电阻3.3R 1% 1/16W 0402; 规格编号: 0402WGF330KTCE; 规格书: 厚声-无铅厚膜电阻.pdf; 价格: 0.003117; 类别: 贴片电阻0402; 品牌: 厚声; 生命周期: 量产; 条码: EBFCIS221116113428
R16 R20 R25 R29 R30 R32 R35 R36 R40-R43 R46 R47 R61 R65 R73 R161-R164 R176 R185 R188 R200 R205 = RES: 规格: 贴片电阻10K 1% 1/16W 0402; 规格编号: 0402WGF1002TCE; 规格书: 厚声-无铅厚膜电阻.pdf; 价格: 0.002773; 类别: 贴片电阻0402; 品牌: 厚声; 生命周期: 量产; 条码: EBF29070046
R18 = RES: 规格: 贴片电阻75K 1% 1/16W 0402; 规格编号: RC0402FR-0775KL; 规格书: 国巨贴片电阻.pdf; 价格: 0.002211; 类别: 贴片电阻0402; 品牌: 国巨; 生命周期: 量产; 条码: EBFCIS221202111303
R22 R211 R215 = RES: 规格: 贴片电阻NC 预留; 类别: 贴片电阻0402; 条码: EBF29070087
U1 U2 U28 U29 = LPW5209AB5F: 规格: 集成电源开关 导通电阻：80mΩ 最大可设置保护电流：2.1A 输入电压：2.5V~6V 静态电流：30uA 其他功能：软启动、短路保护、热保护; 规格书: 微源半导体_LPW5209AB5F.pdf; 价格: 0.468063; 类别: 功率开关; 品牌: 微源半导体; 生命周期: 量产; 条码: EBF29280015
U3 U30 = TP6327GS6: 备注: RK3566金手指与BTB底板替换物料; 规格: DC-DC电源芯片 可输出电流 3A 开关工作频率 600kHz 输出类型 ADJ 输入电压范围：4V-18V; 规格书: 安森德_ASP9135ZC-R.pdf; 类别: 电源管理-DCDC; 品牌: 安森德; 生命周期: 量产; 条码: EBFCIS240710113940
U4 = MP8759GD-Z: 规格: DC-DC电源芯片 输入：4.5V-26V 电流：8A 频率: 固定700KHz频率  FB：0.6V; 规格书: MPS_MP8759GD-Z.pdf; 价格: 3.2; 类别: 电源管理-DCDC; 品牌: MPS; 生命周期: 量产; 条码: EBFCIS221112174800
C43-C45 C212 = CAP_NP: Voltage: 50V; 规格: 贴片电容10nF 10% 50V X7R 0402; 规格编号: CC0402KRX7R9BB103; 规格书: 国巨-贴片电容.pdf; 价格: 0.003808; 类别: 贴片电容0402; 品牌: 国巨; 生命周期: 量产; 条码: EBF29060245
C48 C186 C188 = CAP_NP: Voltage: 10V; 规格: 贴片电容1uF 10% 10V X5R 0402; 规格编号: 0402X105K100NT; 规格书: 风华电容.pdf; 价格: 0.01191; 类别: 贴片电容0402; 品牌: 风华; 生命周期: 量产; 条码: EBF29060121
D3 D4 = LED: 规格: 贴片LED GREEN 正向电流20mA 0603 正贴; 规格编号: EL0603/GHC-C01/DT; 规格书: LED0603-RED.pdf; 类别: 贴片LED; 品牌: 亿光; 生命周期: 量产; 条码: EBF29140043
J7 = 1X4PIN: 规格: 直针XH2.54-4P 间距2.54MM 拔插式 接插件 直插; 规格书: 博穆精密-XH2.54.pdf; 价格: 0.041116; 可替代料: EBF29040012; 类别: XH连接器; 品牌: 博穆精密; 生命周期: 量产; 条码: EBF29040012
LED1 = LED: 规格: 贴片LED RED 正向电流30mA 反向电压9V 功率消耗350mW 0603; 规格编号: 35B00617LGY-RED; 规格书: LED0603-RED.pdf; 类别: 贴片LED; 品牌: 亿光; 生命周期: 量产; 条码: EBF29140007
R26 R27 = RES: 规格: 贴片电阻560R 1% 1/16W 0402; 规格编号: 0402WGF5600TCE; 规格书: 厚声-无铅厚膜电阻.pdf; 价格: 0.002258; 类别: 贴片电阻0402; 品牌: 厚声; 生命周期: 量产; 条码: EBF29070272
R28 R31 R33 R60 R180 R181 R192 R239 = RES: 规格: 贴片电阻100R 1% 1/16W 0402; 规格编号: RI0402L1000FT; 规格书: 合科泰-RI系列电阻.pdf; 类别: 贴片电阻0402; 品牌: 合科泰; 生命周期: 量产; 条码: EBF29070053
R34 R37 R62 R64 R70 R72 R177 R214 = RES: 规格: 贴片电阻4.7K 1% 1/16W 0402; 规格编号: RI0402L4701FT; 规格书: 合科泰-RI系列电阻.pdf; 类别: 贴片电阻0402; 品牌: 合科泰; 生命周期: 量产; 条码: EBF29070047
R44 R45 R48 R53-R55 R57-R59 R178 R179 R190 R191 R193-R195 R197 R198 = RES: 规格: 贴片电阻22R 1% 1/16W 0402; 规格编号: RI0402L22R0FT; 规格书: 合科泰-RI系列电阻.pdf; 类别: 贴片电阻0402; 品牌: 合科泰; 生命周期: 量产; 条码: EBF29070181
SW1-SW6 = SW_PB_ESW: 备注: 修正封装; 规格: 3×4×2.5 160gf 轻触开关 白色; 规格编号: TS-1089U-AR02526; 规格书: 讯普3×4×2.5160GF轻触开.pdf; 价格: 0.168282; 类别: 贴片轻触开关; 品牌: 讯普; 生命周期: 量产; 条码: EBF29310006
U5 U6 = 74LVC1G125: 规格: 时钟缓冲器 驱动器 具有三态输出 允许工作电压为3.3V 5.5V 典型工作电流100mA; 规格书: 74LVC1G125GW.pdf; 价格: 0.182409; 类别: 隔离器件; 品牌: 安世; 生命周期: 量产; 丝印: VM; 条码: EBF29170001
U7 = IRM-V838M3-C_TR1: 规格: 侧贴红外遥控接收头 工作电压2.7V~5.5V 兼容TTL与CMOS; 规格书: IRM-V838M3-C_TR1.pdf; 类别: 红外接收头; 品牌: 亿光; 生命周期: 量产; 条码: EBF29230005
D6 D11-D17 Z1-Z12 = DIODE_BI-DIR_TRIG: 规格: 用于 USB3.0、HDMI 0.5pF、5V、±15kV ESD 保护二极管; 规格书: KLXES15AAA1.pdf; 价格: 0.09719; 类别: 贴片ESD; 品牌: 永裕泰; 生命周期: 量产; 条码: EBF29140063
C49 C174 C176-C179 C192 = CAP_NP: voltage: 10V; 规格: 贴片电容1uF 10% 10V X5R 0402; 规格编号: 0402X105K100NT; 规格书: 风华电容.pdf; 价格: 0.01191; 类别: 贴片电容0402; 品牌: 风华; 生命周期: 量产; 条码: EBF29060121
C51 C52 = CAP_NP: voltage: 50V; 规格: 贴片电容18pF 5% 50V C0G 0402; 规格编号: 0402CG180J500NT; 规格书: 风华电容.pdf; 价格: 0.00515; 类别: 贴片电容0402; 品牌: 风华; 生命周期: 量产; 条码: EBF29060235
C54 C58 C160 C161 = CAP_NP: Voltage: 10V; 规格: 贴片电容4.7uF 10% 10V X5R 0402; 规格编号: CC0402KRX5R6BB475; 规格书: 国巨-贴片电容.pdf; 价格: 0.059058; 类别: 贴片电容0402; 品牌: 国巨; 生命周期: 量产; 条码: EBF29060248
D5 = BAT54C: 规格: 肖特基双二极管 直流反向耐压(Vr) 30V 平均整流电流(Io) 300mA 正向压降(Vf) 1V@100mA; 规格书: 江苏长电_BAT54C.pdf; 价格: 0.077486; 类别: 贴片肖特基二极管; 品牌: 江苏长电; 生命周期: 量产; 丝印: KL3; 条码: EBF29140062
D7-D10 = DIODE_BI-DIR_TRIG: 规格: TVS二极管 箝位电压24.4V 击穿电压16.7V 反向关断电压15V; 规格书: 君耀电子-SMBJ15CA.pdf; 价格: 0.197164; 类别: 贴片TVS; 品牌: 君耀电子; 生命周期: 量产; 条码: EBF29140024
J8 = 1X2PIN: 规格: 间距=1.25mm 直插 2P针座连接器; 规格书: 1.25T-2A.pdf; 类别: 1.25连接器; 品牌: 创都; 生命周期: 量产; 条码: EBF29040105
J9 = CON6: 规格: 绿色插拔式接线端子 间距3.81mm 90度弯针 6PIN; 规格编号: WJ15EDGRC-3.81-6P; 规格书: 康奈克斯电气-绿色端子弯针插座.pdf; 价格: 0.301748; 类别: 绿色插拔式接线端子; 品牌: 康奈克斯电气; 生命周期: 量产; 条码: EBF29040013
J10 = TF_Card: 规格: MICRO SD 卡座 TF T-Flash 外焊 双压片 自弹贴片; 规格编号: TF-015; 规格书: 硕方-TF-015.pdf; 价格: 0.48; 可替代料: EBF29040003; 类别: SD卡连接器; 品牌: 硕方; 生命周期: 量产; 条码: EBF29040003
R56 R170 R171 R173 R184 R187 R189 R199 R201 R217 R219 = RES: 规格: 贴片电阻0R 1% 1/16W 0402; 规格编号: RI0402L000FT; 规格书: 合科泰-RI系列电阻.pdf; 类别: 贴片电阻0402; 品牌: 合科泰; 生命周期: 量产; 条码: EBF29070049
U8 = HYM8563S: 备注: 鲁班猫系列板子; 规格: 工作电压1.5V~5.5V 日期格式YY-MM-DD 时间格式HH:MM:SS 接口类型I2C 电流消耗0.25uA~@3.0V; 规格书: 捷茂微_BM8563EMA.pdf; 价格: 0.8789; 类别: 实时时钟芯片; 品牌: 捷茂微; 生命周期: 量产; 条码: EBFCIS240229100017
U9 = MAX3232CSE: 备注: 鲁班猫; 规格: RS232芯片 收发器 驱动器/接收器数：2/2 协议类别RS232 电源电压3.0V~5.5V 数据速率96kbps; 规格书: 芯力特_SIT3232E-V1.17-cn.pdf; 类别: RS232芯片; 品牌: 芯力特; 生命周期: 量产; 条码: EBFCIS231207155139
Y1 = CRYSTAL_2P: 规格: 无源晶振32.768KHz 70KΩ 9pF 3215; 规格编号: Q13FC1350000300; 规格书: 爱普生-32.768KHz.pdf; 价格: 2.57; 类别: 贴片晶振 3215; 品牌: 爱普生; 生命周期: 量产; 条码: EBF29100004
C62 C64 C66 C68 C162 C167 C169 C170 C183 = CAP_NP: voltage: 10V; 规格: 贴片电容4.7uF 10% 10V X5R 0402; 规格编号: CC0402KRX5R6BB475; 规格书: 国巨-贴片电容.pdf; 价格: 0.059058; 类别: 贴片电容0402; 品牌: 国巨; 生命周期: 量产; 条码: EBF29060248
D18 D20-D22 D24-D27 = DIODE_BI-DIR_TRIG: 规格: TVS二极管 箝位电压11.2V 击穿电压7.22V 反向关断电压6.5V; 规格书: 君耀电子-SMBJ15CA.pdf; 价格: 0.226009; 类别: 贴片TVS; 品牌: 君耀电子; 生命周期: 量产; 条码: EBF29140023
D19 D23 = DIODE_SCHTKY: 规格: 直流反向耐压(Vr)：30V 平均整流电流(Io)：200mA 正向压降(Vf)：500mV@200mA 30V@100mA,VF=350mV@10mA; 规格书: 江苏长电_RB521S-30.pdf; 价格: 0.06781; 类别: 贴片肖特基二极管; 品牌: 江苏长电; 生命周期: 量产; 条码: EBFCIS221114153437
J11 J13 J29 = 1X2PIN: 规格: 蓝色直插单排排针 总PIN数2 间距2.54mm; 规格编号: HDR1X2-2R54-TM-VM-BLUE; 规格书: 州日_单排针_直插_2P54.pdf; 价格: 0.02; 类别: 2.54mm直插单排排针; 品牌: 州日; 生命周期: 量产; 条码: EBF29020019
J12 J14 = CON4: 规格: 插拔式接线端子 间距3.81mm 90度弯针 4PIN; 规格书: 康奈克斯电气-绿色端子弯针插座.pdf; 价格: 0.198381; 类别: 绿色插拔式接线端子; 品牌: 康奈克斯电气; 生命周期: 量产; 条码: EBF29040009
R63 R71 R78 R79 = RES: 规格: 贴片电阻120R 1% 1/10W 0603; 规格编号: RI0603L1200FT; 规格书: 合科泰-RI系列电阻.pdf; 类别: 贴片电阻0603; 品牌: 合科泰; 生命周期: 量产; 条码: EBF29070067
U10 U11 = SIT3088E-8P: 备注: 鲁班猫; 规格: RS-485/RS-422芯片 收发器 允许256个器件连接总线 协议类别RS-485 电源电压3.0V~5.5V 数据速率14Mbps; 规格书: 芯力特_SIT3088E-V1.8_cn.pdf; 类别: RS485/RS422芯片; 品牌: 芯力特; 生命周期: 量产; 条码: EBFCIS231207153322
U12 U13 = TJA1057GT3_8P: 备注: 替代TJA1042T/3/1J; 规格: CAN芯片 收发器 驱动器/接收器数：1/1 协议类别CAN总线 电源电压4.5V~5.5V 数据速率5Mbps; 规格书: 芯力特_SIT1042.pdf; 价格: 1.98; 类别: CAN芯片; 品牌: 芯力特; 生命周期: 量产; 条码: EBFCIS230524153230
J21-J24 = FPC-24P: 规格: FPC连接器 针脚数24 间距0.5mmm 下接 卧贴 翻盖式; 规格编号: AFC01-S24FCA-00; 规格书: 钜硕电子-FPC间距0.5mm.pdf; 价格: 0.368739; 可替代料: EBF29040059; 类别: FPC连接器; 品牌: 钜硕电子; 生命周期: 量产; 条码: EBF29040059
C151 = CAP: voltage: 6.3V; 规格: 贴片电容220uF 20% 6.3V 坦电容 CASE-B_3528; 规格编号: TLJB227M006R0500; 规格书: AVX_贴片坦电容.pdf; 价格: 1.28; 类别: 贴片坦电容; 品牌: AVX; 生命周期: 量产; 条码: EBF29060264
C153-C155 = CAP_NP: Voltage: 50V; 规格: 贴片电容33pF 5% 50V 0402; 规格编号: 0402CG330J500NT; 规格书: 风华电容.pdf; 类别: 贴片电容0402; 品牌: 风华; 生命周期: 量产; 条码: EBF29060298
J25 = MINI-PCIE: 规格: MINI PCIE插座 引脚数：52P; 规格编号: PCIE-52P56H; 规格书: XUNPU(讯普)_52PMINIPCIE插座.pdf; 价格: 1.935; 可替代料: EBF29040055; 类别: 金手指连接器; 品牌: 讯普; 生命周期: 量产; 条码: EBF29040055
J31 = SIM-7-1: 规格: nano sim卡座; 规格编号: HYC63-SIM07-137; 规格书: 华宇创_NANOSIMPUSH1.37H带CDPIN带柱.pdf; 价格: 1.48; 可替代料: EBF29040054; 类别: SIM卡座连接器; 品牌: 华宇创; 生命周期: 量产; 条码: EBF29040054
R169 = RES: 规格: 贴片电阻15K 1% 1/16W 0402; 规格编号: RI0402L1502FT; 规格书: 合科泰-RI系列电阻.pdf; 类别: 贴片电阻0402; 品牌: 合科泰; 生命周期: 量产; 条码: EBF29070222
R182 R183 = RES: 规格: 贴片电阻2.2R 1% 1/16W 0402; 规格编号: 0402WGF220KTCE; 规格书: 厚声-无铅厚膜电阻.pdf; 价格: 0.003072; 类别: 贴片电阻0402; 品牌: 厚声; 生命周期: 量产; 条码: EBF29070280
SS5 SS6 = SPACER: 规格: SMT贴片螺母M2.5 台阶高度1.4MM 台阶外径：4.09MM 螺柱长度：3MM; 规格编号: SMTSO2530CTJ; 规格书: 雄和远景_SMTSO2530CTJ.pdf; 类别: 贴片螺母; 品牌: 雄和远景; 生命周期: 量产; 条码: EBFCIS221028102827
U32 = NUP5120-D: 规格: 防静电保护ESD二极管 击穿电压6.2V 反向关断电压5V 封装SOT-523; 规格书: 安森美_NUP5120X6T1G.pdf; 价格: 0.39; 类别: 贴片ESD; 品牌: 安森美; 生命周期: 量产; 条码: EBF29140034
C164 C172 = CAP_NP: voltage: 25V; 规格: 贴片电容10uF 20% 25V X5R 0603; 规格编号: CL10A106MA8NRNC; 规格书: 三星电容.pdf; 价格: 0.109811; 类别: 贴片电容0603; 品牌: 三星; 生命周期: 量产; 条码: EBF29060171
C180-C182 = CAP_NP: voltage: 10V; 规格: 贴片电容10uF 20% 10V X5R 0402; 规格编号: CL05A106MP8NUB8; 规格书: 三星电容.pdf; 价格: 0.518415; 类别: 贴片电容0402; 品牌: 三星; 生命周期: 量产; 条码: EBF29060247
C184 = CAP_NP: voltage: 50V; 规格: 贴片电容100pF 5% 50V C0G 0402; 规格编号: GRT1555C1H101JA; 规格书: 村田040系列贴片电容.pdf; 价格: 0.034837; 类别: 贴片电容0402; 品牌: 村田; 生命周期: 量产; 条码: EBF29060302
C185 = CAP_NP: voltage: 25V; 备注: 新增0402物料; 规格: 贴片电容0.22uF 20% 25V X7R 0402; 规格编号: TCC0402X7R224K250AT; 规格书: CCTC_TCC0402X5R105K6R3AT; 价格: 0.0073; 类别: 贴片电容0402; 品牌: CCTC; 生命周期: 量产; 条码: EBFCIS241220094109
C189 = CAP_NP: voltage: 10V; 规格: 贴片电容22uF 20% 10V X5R 0603; 规格编号: CL10A226MP8NUNE; 规格书: 三星电容.pdf; 价格: 0.078818; 类别: 贴片电容0603; 品牌: 三星; 生命周期: 量产; 条码: EBF29060163
C191 C193 = CAP_NP: voltage: 10V; 规格: 贴片电容47uF 20% 10V X5R 0805; 规格编号: 0805X476M100NT; 规格书: 风华电容.pdf; 价格: 0.368494; 类别: 贴片电容0805; 品牌: 风华; 生命周期: 量产; 条码: EBF29060212
C194 = CAP_NP: Voltage: 50V; 规格: 贴片电容100pF 5% 50V C0G 0603; 规格编号: 0603CG101J500NT; 规格书: 风华电容.pdf; 价格: 0.014181; 类别: 贴片电容0603; 品牌: 风华; 生命周期: 量产; 条码: EBF29060132
J26 = MIC_JACK: 规格: 音频插座 耳机插座 双声道 3.5mm耳机座 5脚 绿; 规格书: 星坤-音频连接器.pdf; 价格: 0.24; 可替代料: EBF29020024; 类别: 耳机座; 品牌: 中国星坤; 生命周期: 量产; 条码: EBF29020024
J27 = MIC_JACK: 规格: 音频插座 耳机插座 双声道 3.5mm耳机座 5脚 粉; 规格书: 星坤-音频连接器.pdf; 价格: 0.24; 可替代料: EBF29020023; 类别: 耳机座; 品牌: 中国星坤; 生命周期: 量产; 条码: EBF29020023
J28 = 1X2PIN: 规格: 直针PH2.0-2P 间距2.0MM 拔插式 接插件; 规格书: 博穆精密_PH2.0-A.pdf; 价格: 0.019031; 可替代料: EBF29040005; 类别: PH连接器; 品牌: 博穆精密; 生命周期: 量产; 条码: EBF29040005
P1 = MIC_POM: 规格: 4*1.2mm咪头 双电容驻极体话筒 拾音器 工作电压1.5V-10V 灵敏度-62DB 低阻抗; 规格编号: GMI4015P-2C-62db; 规格书: 赢海_GMI4015P-2C-62db.pdf; 价格: 0.868384; 类别: 麦克风; 品牌: 赢海; 生命周期: 量产; 条码: EBFCIS221130183008
Q16 Q17 = MOSFET_N: 备注: 立创停售; 规格: N沟道MOS 导通电阻47mΩ 电流3.6A 4.5V 阈值电压(Vgs(th)@Id)1V 连续漏极电流2.9A; 规格书: WNM2016-3_TR.pdf; 类别: N-MOS; 品牌: 韦尔; 条码: EBF29280014
R186 = RES: 规格: 贴片电阻4.7R 1% 1/16W 0402; 规格编号: 0402WGF470KTCE; 规格书: 厚声-无铅厚膜电阻.pdf; 价格: 0.003317; 类别: 贴片电阻0402; 品牌: 厚声; 生命周期: 量产; 条码: EBFCIS221112135607
R196 R202 = RES: 规格: 贴片电阻1.1K 1% 1/16W 0402; 规格编号: 0402WGF1101TCE; 规格书: 厚声-无铅厚膜电阻.pdf; 价格: 0.001622; 类别: 贴片电阻0402; 品牌: 厚声; 生命周期: 量产; 条码: EBFCIS221112135212
R207 = RES: 规格: 贴片电阻120R 1% 1/16W 0402; 规格编号: 0402WGF1200TCE; 规格书: 厚声-无铅厚膜电阻.pdf; 价格: 0.002198; 类别: 贴片电阻0402; 品牌: 厚声; 生命周期: 量产; 条码: EBF29070275
R208 R218 = RES: 规格: 贴片电阻2.2K 1% 1/16W 0402; 规格编号: RI0402L2201FT; 规格书: 合科泰-RI系列电阻.pdf; 类别: 贴片电阻0402; 品牌: 合科泰; 生命周期: 量产; 条码: EBF29070051
R216 = RES: 规格: 贴片电阻300K 1% 1/16W 0402; 规格编号: RI0402L3003FT; 规格书: 合科泰-RI系列电阻.pdf; 类别: 贴片电阻0402; 品牌: 合科泰; 生命周期: 量产; 条码: EBF29070220
U33 = ES8388: 规格: 音频接口芯片 模拟供电1.7V~3.6V 核心与IO供电1.5V~3.6V; 规格书: 顺芯_ES8388.pdf; 价格: 3.904; 类别: 音频芯片; 品牌: 顺芯; 条码: EBFCIS221116105415
U34 = 8002A: 规格: 桥式音频功率放大器 输出功率高（4Ω 1KHz）宽工作电压范围2.2V-5.5V 输出不需要外接耦合电容或上举电容 缓冲网络 反馈电阻; 规格书: 英锐芯_8002A.pdf; 价格: 0.475235; 类别: 音频芯片; 品牌: 英锐芯; 生命周期: 量产; 条码: EBF29200006

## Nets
GND: C1.2 C2.2 C3.2 C4.2 C5.2 C6.2 C7.2 C8.2 C11.2 C12.2 C13.2 C14.2 C15.2 C16.2 C17.2 C18.1 C19.2 C21.2 C22.2 C23.2 C24.2 C25.2 C26.2 C27.2 C28.2 C29.2 C30.2 C39.2 C40.2 C41.2 C42.2 C43.2 C44.2 C45.2 C46.2 C47.2 C48.2 C49.2 C50.2 C51.2 C52.2 C53.2 C54.2 C55.2 C58.2 C59.2 C60.2 C61.2 C62.2 C63.2 C64.2 C65.2 C66.2 C67.2 C68.2 C69.2 C139.2 C140.2 C141.2 C142.2 C143.2 C144.2 C147.2 C148.2 C149.2 C150.2 C151.2 C152.2 C153.2 C154.2 C155.2 C158.2 C159.2 C160.2 C161.2 C162.2 C163.2 C164.2 C165.2 C166.2 C167.2 C168.2 C169.2 C170.2 C171.2 C172.2 C173.2 C174.2 C175.2 C180.2 C181.2 C182.2 C183.2 C186.2 C187.2 C188.2 C189.2 C190.2 C192.2 C195.2 C212.2 D1.1 D2.2(A) D6.1 D7.1 D8.1 D9.1 D10.1 D11.1 D12.1 D13.1 D14.1 D15.1 D16.1 D17.1 D18.1 D20.1 D21.1 D22.1 D24.1 D25.1 D26.1 D27.1 J1.1 J1.2 J1.3 J1.5 J2.2 J7.4 J8.2 J9.2 J9.5 J10.6(VSS) J10.10(GND10) J10.11(GND11) J10.12(GND12) J10.13(GND13) J21.4 J21.18 J21.21 J21.23 J21.24 J21.25(SH1) J21.26(SH2) J22.4 J22.18 J22.21 J22.23 J22.24 J22.25(SH1) J22.26(SH2) J23.4 J23.18 J23.21 J23.23 J23.24 J23.25(SH1) J23.26(SH2) J24.4 J24.18 J24.21 J24.23 J24.24 J24.25(SH1) J24.26(SH2) J25.4(GND9) J25.9(GND1) J25.15(GND2) J25.18(GND10) J25.21(GND3) J25.26(GND11) J25.27(GND4) J25.29(GND5) J25.34(GND12) J25.35(GND6) J25.37(GND7) J25.40(GND13) J25.43(GND8) J25.50(GND14) J25.53 J25.54 J31.5(GND) J31.8(SH1) J31.9(SH2) J31.10(SH3) J31.11(SH4) Q2.2(EMITTER) Q3.2(EMITTER) Q4.2(EMITTER) Q5.2(EMITTER) R4.2 R5.2 R7.2 R9.2 R16.2 R17.1 R20.2 R22.1 R40.2 R41.2 R42.2 R64.2 R65.2 R72.2 R73.2 R166.2 R168.2 R174.2 R176.2 R202.2 R211.1 R214.2 R215.1 R217.2 R218.2 R219.2 SS5.1(NC) SS6.1(NC) SW1.1(A1) SW1.2(A2) SW2.1(A1) SW2.2(A2) SW3.1(A1) SW3.2(A2) SW4.1(A1) SW4.2(A2) SW5.1(A1) SW5.2(A2) SW6.1(A1) SW6.2(A2) U1.2(GND) U2.2(GND) U3.1(GND) U4.2(PGND) U4.10(AGND) U5.1(\\~{O}E) U5.3(GND) U6.1(\\~{O}E) U6.3(GND) U7.1(GND1) U7.4(GND2) U8.4(VSS) U9.15(GND) U10.5(GND) U11.5(GND) U12.2(GND) U12.8(S) U13.2(GND) U13.8(S) U28.2(GND) U29.2(GND) U30.1(GND) U32.2 U33.4(DGND) U33.13(HPGND) U33.18(AGND) U33.29(EPAD) U34.7(GND) Z1.1 Z2.1 Z3.2 Z4.2 Z5.1 Z6.1 Z7.1 Z8.1 Z9.1 Z10.1 Z11.1 Z12.1 ; also on sheet 1 2 6 7 8 9 10
VCC3V3_SYS: C10.1 C15.1 C16.1 C17.1 L1.2 R2.1 R6.1 ; also on sheet 10
VCC5V0_SYS: C25.1 C26.1 C27.1 C28.1 C29.1 C189.1 C190.1 L2.2 R11.1 R18.1 R34.1 R35.1 R36.1 U2.5(IN) U4.5(VOUT) U28.5(IN) U29.5(IN) U34.6(VCC) ; also on sheet 1 6 8 10
VCC_1V8_S0: R185.1 R188.1 ; also on sheet 6
VCC_1V8_S3: R46.1 R47.1 R61.1 ; also on sheet 6
VCC_3V3_S3: C11.1 C40.1 C42.1 D5.2 R1.1 R25.1 R29.1 R56.1 U5.5(VCC) U6.5(VCC) ; also on sheet 1 6
VCC_3V3_SD: C58.1 C59.1 J10.4(VDD) R56.2
VCC_12V: C1.1 C2.1 C3.1 C12.1 C13.1 C14.1 C19.1 C21.1 C22.1 C23.1 C147.1 C148.1 C149.1 D1.2 F1.2 R8.1 R10.1 R15.1 U3.3(VIN) U4.1(VIN) U30.3(VIN)
VCCA1V8_CODEC: C164.1 C165.1 C174.1 C175.1 C187.1 R184.2 R200.1 R207.1 U33.2(DVDD) U33.3(PVDD)
VCCA3V3_CODEC: C172.1 C173.1 R186.1 R187.1 R189.2 R192.2 R205.1
VCCA_1V8_S0: C162.1 C163.1 R30.2 R32.2 R184.1 ; also on sheet 6
VCCA_3V3_S0: C170.1 C171.1 R189.1 ; also on sheet 6
VDD_3V3: C5.1 C6.1 C54.1 C60.1 C61.1 C62.1 C63.1 C66.1 C67.1 D19.2 D23.2 R43.1 R44.1 R161.1 R162.1 R163.1 R164.1 U1.1(OUT) U9.16(VCC) U10.8(VCC) U11.8(VCC) U12.5(VIO) U13.5(VIO) ; also on sheet 2 7 8 9 10
VDD_5V: C7.1 C8.1 C64.1 C65.1 C68.1 C69.1 U2.1(OUT) U12.3(VCC) U13.3(VCC) ; also on sheet 9
5V0_CAM0/1: C140.1 C141.1 J21.1 J21.2 J21.3 J22.1 J22.2 J22.3 U28.1(OUT)
5V0_CAM2/3: C143.1 C144.1 J23.1 J23.2 J23.3 J24.1 J24.2 J24.3 U29.1(OUT)
BAT_RTC: C50.1 D5.1 D6.2 J8.1
CAM0/1_PWR_EN: R165.1 ; also on sheet 6
CAM0_nRST: J21.22 ; also on sheet 6
CAM0_PWDN: J21.15 ; also on sheet 6
CAM1_nRST: J22.22 ; also on sheet 6
CAM1_PWDN: J22.15 ; also on sheet 6
CAM2/3_PWR_EN: R167.1 ; also on sheet 6
CAM2_nRST: J23.22 ; also on sheet 6
CAM2_PWDN: J23.15 ; also on sheet 6
CAM3_nRST: J24.22 ; also on sheet 6
CAM3_PWDN: J24.15 ; also on sheet 6
CAN1_H: D24.2 R74.1 R78.1 U12.7(CANH)
CAN1_L: D25.2 R75.1 R78.2 U12.6(CANL)
CAN1_RX_M1: U12.4(RXD) ; also on sheet 6
CAN1_TX_M1: U12.1(TXD) ; also on sheet 6
CAN2_H: D26.2 R76.1 R79.1 U13.7(CANH)
CAN2_L: D27.2 R77.1 R79.2 U13.6(CANL)
CAN2_RX_M0: U13.4(RXD) ; also on sheet 6
CAN2_TX_M0: U13.1(TXD) ; also on sheet 6
DBG_RX: R27.2 U6.2(A)
DBG_RXD: J7.3 R27.1 Z4.1
DBG_TX: R26.2 U5.4(Y)
DBG_TXD: J7.2 R26.1 Z3.1
DEBUG_RX: R29.2 U6.4(Y) ; also on sheet 6
DEBUG_TX: R25.2 U5.2(A) ; also on sheet 6
EARPHONE_CTL: R216.1 ; also on sheet 6
EXT_PWR_EN: R3.1 R37.1 ; also on sheet 6
FAN: C24.1 Q1.2(SOURCE) R10.2 R11.2 R12.1
FAN_PWM: R13.1 ; also on sheet 6
HP_PLUG_IN_DET: C186.1 R206.1 ; also on sheet 6
HUB_DM4: R182.2 ; also on sheet 8
HUB_DP4: R183.2 ; also on sheet 8
I2C0_SCL_M2: U8.6(SCL) ; also on sheet 6
I2C0_SDA_M2: U8.5(SDA) ; also on sheet 6
I2C1_SCL_M2: J23.6 R163.2 ; also on sheet 1 6
I2C1_SDA_M2: J23.5 R161.2 ; also on sheet 1 6
I2C2_SCL_M4: J21.6 ; also on sheet 6 10
I2C2_SDA_M4: J21.5 ; also on sheet 6 10
I2C5_SCL_M3: J22.6 ; also on sheet 6 10
I2C5_SDA_M3: J22.5 ; also on sheet 6 10
I2C7_SCL_M0_CODEC: R185.2 R197.1 ; also on sheet 6
I2C7_SDA_M0_CODEC: R188.2 R198.1 ; also on sheet 6
I2C8_SCL_M2: J24.6 R164.2 ; also on sheet 6
I2C8_SDA_M2: J24.5 R162.2 ; also on sheet 6
I2C_ADDR_SET: R200.2 U33.26(CE)
I2S0_LRCK: R194.1 ; also on sheet 6
I2S0_MCLK: R190.1 ; also on sheet 6
I2S0_SCLK: R191.1 ; also on sheet 6
I2S0_SDI0: R195.1 ; also on sheet 6
I2S0_SDO0: R193.1 ; also on sheet 6
MIC1_L: C176.2 C194.1 J27.2 J27.4 J29.1 R208.2 Z8.2
MIC1_R: C177.2 C194.2 J27.3 J27.5 J29.2 R218.1 Z11.2
MIC2_L: C178.2 R199.2
MIC2_R: C179.2 R201.2
MINIPCIE_3V3: C146.1 C150.1 C151.1 C152.1 C158.1 C159.1 C160.1 C161.1 J25.2(VBAT1) J25.24(VBAT5) J25.39(VBAT2) J25.41(VBAT3) J25.52(VBAT4) L6.2 R172.1 R177.1
MINIPCIE_nWDISABLE: R180.2 ; also on sheet 6
MINIPCIE_PWR_EN: R175.1 ; also on sheet 6
MIPI_CSI0_RX_CLK0N: J23.10 ; also on sheet 6
MIPI_CSI0_RX_CLK0P: J23.9 ; also on sheet 6
MIPI_CSI0_RX_CLK1N: J24.10 ; also on sheet 6
MIPI_CSI0_RX_CLK1P: J24.9 ; also on sheet 6
MIPI_CSI0_RX_D0N: J23.12 ; also on sheet 6
MIPI_CSI0_RX_D0P: J23.11 ; also on sheet 6
MIPI_CSI0_RX_D1N: J23.8 ; also on sheet 6
MIPI_CSI0_RX_D1P: J23.7 ; also on sheet 6
MIPI_CSI0_RX_D2N: J24.12 ; also on sheet 6
MIPI_CSI0_RX_D2P: J24.11 ; also on sheet 6
MIPI_CSI0_RX_D3N: J24.8 ; also on sheet 6
MIPI_CSI0_RX_D3P: J24.7 ; also on sheet 6
MIPI_DPHY0_RX_CLKN: J21.10 ; also on sheet 6
MIPI_DPHY0_RX_CLKP: J21.9 ; also on sheet 6
MIPI_DPHY0_RX_D0N: J21.12 ; also on sheet 6
MIPI_DPHY0_RX_D0P: J21.11 ; also on sheet 6
MIPI_DPHY0_RX_D1N: J21.8 ; also on sheet 6
MIPI_DPHY0_RX_D1P: J21.7 ; also on sheet 6
MIPI_DPHY0_RX_D2N: J21.17 ; also on sheet 6
MIPI_DPHY0_RX_D2P: J21.16 ; also on sheet 6
MIPI_DPHY0_RX_D3N: J21.20 ; also on sheet 6
MIPI_DPHY0_RX_D3P: J21.19 ; also on sheet 6
MIPI_DPHY1_RX_CLKN: J22.10 ; also on sheet 6
MIPI_DPHY1_RX_CLKP: J22.9 ; also on sheet 6
MIPI_DPHY1_RX_D0N: J22.12 ; also on sheet 6
MIPI_DPHY1_RX_D0P: J22.11 ; also on sheet 6
MIPI_DPHY1_RX_D1N: J22.8 ; also on sheet 6
MIPI_DPHY1_RX_D1P: J22.7 ; also on sheet 6
MIPI_DPHY1_RX_D2N: J22.17 ; also on sheet 6
MIPI_DPHY1_RX_D2P: J22.16 ; also on sheet 6
MIPI_DPHY1_RX_D3N: J22.20 ; also on sheet 6
MIPI_DPHY1_RX_D3P: J22.19 ; also on sheet 6
OUT1_L: C191.1 U33.12(LOUT1)
OUT1_R: C193.1 U33.11(ROUT1)
OUT2_L: R203.1 U33.15(LOUT2)
OUT2_R: R204.1 U33.14(ROUT2)
PCIE20_0_CLKN: J25.11(VDD-EXT) ; also on sheet 6
PCIE20_0_CLKP: J25.13(RESERVED) ; also on sheet 6
PCIE20_0_RXN: J25.23(UART-RXD) ; also on sheet 6
PCIE20_0_RXP: J25.25(UART-RTS) ; also on sheet 6
PCIE20_0_TXN: C156.1 ; also on sheet 6
PCIE20_0_TXP: C157.1 ; also on sheet 6
PCIE20x1_2_CLKREQn_M0: R179.1 ; also on sheet 6
PCIE20x1_2_PERSTn_M0: R181.2 ; also on sheet 6
PCIE20x1_2_WAKEn_M0: R178.1 ; also on sheet 6
PE_TXN: C156.2 J25.31(UART-TXD)
PE_TXP: C157.2 J25.33(PERST2)
PWM7_IR_M0: C46.1 R45.1 ; also on sheet 6
PWRON_KEY: C39.1 SW1.3(B1) SW1.4(B2) Z1.2 ; also on sheet 6
RESET_KEY: C41.1 SW2.3(B1) SW2.4(B2) Z2.2 ; also on sheet 6
RS485_1_A: D20.2 J11.1 R62.2 R67.1 U10.6(A)
RS485_1_B: D18.2 R63.1 R64.1 R66.1 U10.7(B)
RS485_2_A: D22.2 J13.1 R69.1 R70.2 U11.6(A)
RS485_2_B: D21.2 R68.1 R71.1 R72.1 U11.7(B)
RTC_32K_IN: R48.2 ; also on sheet 6
RTC_INT: R46.2 U8.3(\\~{IN}T) ; also on sheet 6
RXD1_232: D8.2 R51.1 U9.13(R1IN)
RXD2_232: D7.2 R49.1 U9.8(R2IN)
SARADC_BOOT: R239.2 ; also on sheet 6
SARADC_IN1/REC: R28.2 ; also on sheet 6
SARADC_IN4: R31.2 ; also on sheet 6
SARADC_IN5: R33.2 ; also on sheet 6
SDMMC_CLK: R57.1 ; also on sheet 6
SDMMC_CMD: R55.1 ; also on sheet 6
SDMMC_D0: R58.1 ; also on sheet 6
SDMMC_D1: R59.1 ; also on sheet 6
SDMMC_D2: R53.1 ; also on sheet 6
SDMMC_D3: R54.1 ; also on sheet 6
SDMMC_DET: R60.1 R61.2 ; also on sheet 6
SIM_CLK0: J25.12(USIM-CLK) R171.1
SIM_DATA0: J25.10(USIM-DATA) R173.1
SIM_RST0: J25.14(USIM-RST) R170.1
SIM_VDD: J25.8(USIM-VDD) J31.1(VCC) R169.1 U32.1
SPK_CTRL: R214.1 U34.1(SDN) ; also on sheet 6
SYS_LED: R38.1 ; also on sheet 6
TXD1_232: D10.2 R52.1 U9.14(T1OUT)
TXD2_232: D9.2 R50.1 U9.7(T2OUT)
UART0_RX_M0: U9.9(R2OUT) ; also on sheet 6
UART0_TX_M0: U9.10(T2IN) ; also on sheet 6
UART4_DIR: R65.1 U10.2(~{RE}) U10.3(DE) ; also on sheet 6
UART4_RX_M2: U10.1(RXD) ; also on sheet 6
UART4_TX_M2: U10.4(TXD) ; also on sheet 6
UART7_DIR: R73.1 U11.2(~{RE}) U11.3(DE) ; also on sheet 6
UART7_RX_M2: U11.1(RXD) ; also on sheet 6
UART7_TX_M2: U11.4(TXD) ; also on sheet 6
UART9_RX_M2: U9.12(R1OUT) ; also on sheet 6
UART9_TX_M2: U9.11(T1IN) ; also on sheet 6
USER_LED: R39.1 ; also on sheet 6
N02088: F1.1 J1.4
N03633: C9.1 U3.6(BOOT)
N03641: C9.2 L1.1 U3.2(SW)
N03801: C10.2 R6.2 R7.1 U3.4(FB)
N15118646: R1.2 R2.2 U1.5(IN)
N15118698: C4.1 R3.2 U1.4(EN) U2.4(EN)
N15119063: R4.1 U1.3(ISET)
N15123057: R5.1 U2.3(ISET)
N15659726: C18.2 R8.2 R9.1 U3.5(EN)
N16793147: D11.2 J10.1(DAT2) R53.2
N16793149: D15.2 J10.7(DAT0) R58.2
N16793151: D14.2 J10.5(CLK) R57.2
N16793153: D13.2 J10.3(CMD) R55.2
N16793155: D12.2 J10.2(CD/DAT3) R54.2
N16793157: D16.2 J10.8(DAT1) R59.2
N16793300: D17.2 J10.9(CD) R60.2
N16811933: J25.1(MIC-P) R177.2 R178.2
N16823854: J25.7(SPK-N) R179.2
N16928945: J25.20(W-DISABLE) R180.1
N16929135: J25.22(PERST1) R181.1
N16980859: C155.1 J31.2(RST) R170.2 U32.6
N16980861: C154.1 J31.3(CLK) R171.2 U32.4
N16980863: C153.1 J31.7(I/O) R169.2 R173.2 U32.5
N17454508: C56.2 U9.1(C1+)
N17454513: C56.1 U9.3(C1-)
N17455367: C57.2 U9.4(C2+)
N17455372: C57.1 U9.5(C2-)
N17455499: C55.1 U9.6(V-)
N17455508: C53.1 U9.2(V+)
N17592125: C145.1 U30.6(BOOT)
N17592129: C145.2 L6.1 U30.2(SW)
N17592172: C146.2 R172.2 R174.1 U30.4(FB)
N17592220: R175.2 R176.1 U30.5(EN)
N17697880: R166.1 U28.3(ISET)
N17697953: C139.1 R165.2 U28.4(EN)
N17702194: J12.3 R68.2
N17702199: J12.4 R69.2
N17702222: J12.2 R67.2
N17702231: J12.1 R66.2
N17728858: D19.1 R62.1
N17729021: D23.1 R70.1
N17731608: J9.4 R51.2
N17731627: J9.1 R49.2
N17750545: Q1.1(GATE) Q2.3(COLLECTOR) R12.2
N17750554: D2.1(K) J2.1 Q1.3(DRAIN)
N17750632: Q2.1(BASE) R13.2 R16.1
N17946485: C43.1 R28.1 SW3.3(B1) SW3.4(B2) Z5.2
N18057251: J25.36(USB-D-) R182.1
N18057253: J25.38(USB-D+) R183.1
N18115454: R168.1 U29.3(ISET)
N18115527: C142.1 R167.2 U29.4(EN)
N18211307: C30.1 R19.1 R21.1 U4.9(VCC)
N18211553: C20.2 L2.1 U4.7(SW)
N18211596: R19.2 U4.3(PG)
N18211602: R21.2 R22.2 U4.6(MODE)
N18211651: R18.2 R20.1 U4.11(FB)
N18211688: R14.1 U4.8(BST)
N18211692: C20.1 R14.2
N18213641: R15.2 R17.2 U4.12(EN)
N18312149: R198.2 U33.27(CDATA)
N18312152: R197.2 U33.28(CCLK)
N18312155: R195.2 U33.8(ASDOUT)
N18312158: R194.2 U33.7(LRCK)
N18312161: R193.2 U33.6(DSDIN)
N18312164: R191.2 U33.5(SCLK)
N18312167: R190.2 U33.1(MCLK)
N18314752: C166.1 C167.1 R186.2 U33.17(AVDD)
N18314935: C168.1 C169.1 R187.2 U33.16(HPVDD)
N18315822: C176.1 U33.24(LIN1)
N18315825: C177.1 U33.23(RIN1)
N18315828: C178.1 U33.22(LIN2)
N18315831: C179.1 U33.21(RIN2)
N18315834: C180.1 U33.20(VMID)
N18315837: C181.1 U33.19(ADCVREF)
N18315840: C182.1 U33.10(VREF)
N18319040: C184.1 P1.1(Out) R196.2 R199.1
N18319047: C184.2 P1.2(GND) R201.1 R202.1
N18319296: C183.1 R192.1 R196.1
N18351323: J14.3 R76.2
N18351325: J14.4 R77.2
N18351329: J14.2 R75.2
N18351335: J14.1 R74.2
N18375618: D3.1(CATHODE) Q4.3(COLLECTOR)
N18375621: D3.2(ANODE) R35.2
N18375775: Q4.1(BASE) R38.2 R41.1
N18376132: D4.1(CATHODE) Q5.3(COLLECTOR)
N18376134: D4.2(ANODE) R36.2
N18376144: Q5.1(BASE) R39.2 R42.1
N18458541: C44.1 R30.1 R31.1 SW4.3(B1) SW4.4(B2) Z6.2
N18458605: C45.1 R32.1 R33.1 SW5.3(B1) SW5.4(B2) Z7.2
N18463759: LED1.1(CATHODE) Q3.3(COLLECTOR)
N18463775: LED1.2(ANODE) R34.2
N18463803: Q3.1(BASE) R37.2 R40.1
N18464833: R43.2 R45.2 U7.3(OUT)
N18464854: C47.1 C48.1 R44.2 U7.2(VCC)
N18479746: J26.1 R217.1
N18479761: J26.3 J26.5 Q17.2(SOURCE) Z10.2
N18479774: J26.2 Q16.2(SOURCE) R206.2 Z9.2
N18480030: J26.4 R205.2
N18480910: C188.1 R207.2 R208.1
N18480944: J27.1 R219.1
N18528085: J9.6 R52.2
N18528088: J9.3 R50.2
N18639472: J28.2 R212.2 U34.5(VO1)
N18639500: R209.2 R212.1 U34.4(IN-)
N18639545: C192.1 U34.2(BYPASS) U34.3(IN+)
N18639570: C185.1 R203.2 R204.2
N18639588: C185.2 R209.1
N18642135: C52.1 U8.2(OSCO) Y1.2
N18642163: C51.1 U8.1(OSCI) Y1.1
N18642204: C49.1 D5.3 U8.8(VDD)
N18642319: R47.2 R48.1 U8.7(CLKOUT)
N18645225: Q16.3(DRAIN) R210.2 R211.2
N18645232: Q17.3(DRAIN) R213.2 R215.2
N18645288: C193.2 R213.1
N18645295: C191.2 R210.1
N18645705: C195.1 Q16.1(GATE) Q17.1(GATE) R216.2
N18647092: J28.1 U34.8(VO2)
N18804334: J11.2 R63.2
N18804414: J13.2 R71.2
N18903114: C212.1 R239.1 SW6.3(B1) SW6.4(B2) Z12.2

Not connected (* = marked no-connect by the designer): H1 1(NC)*; H2 1(NC)*; H3 1(NC)*; H4 1(NC)*; J7 1*; J21 13* 14*; J22 13* 14*; J23 13* 14* 16* 17* 19* 20*; J24 13* 14* 16* 17* 19* 20*; J25 3(MIC-N)* 5(SPK-P)* 6(NC1)* 16(RESERVED6)* 17(RESERVED5)* 19(WAKEUP-IN)* 28(UART-CTS)* 30(UART-DCD)* 32(WAKEUP-OUT)* 42(LED-WWAN)* 44(USIM-PRESENCE)* 45(RESERVED1)* 46(UART-DTR)* 47(RESERVED2)* 48(NC2)* 49(RESERVED3)* 51(RESERVED4)*; J31 4(CD)* 6(VPP)*; U4 4(NC)*; U32 3*; U33 9(NC1)* 25(NC2)*

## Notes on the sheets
sheet 11
- MIPI CSI 0 PORT
- MIPI CSI 1 PORT
- GPIO4_A6
- GPIO4_B0
- GPIO4_A7
- GPIO4_A0
- MIPI CSI Power
- MIPI CSI 2 PORT
- MIPI CSI 3 PORT
- GPIO1_D3
- 2A限流
- GPIO4_A1
- GPIO4_B4
- GPIO4_A2
- GPIO4_B5
- GPIO1_D5
- 2A限流
sheet 12
- MINI PCIE POWER
- SIM CARD
- 3.3v 3A
- FB 0.765V
- GPIO0_C6
- MINI PCIE
- GPIO3_A6
sheet 13
- AUDIO CODEC
- MIC
- 7bit i2c address:0x11
- EarPhone PORT
- MIC PORT
- SPK PA
- GPIO0_A0
- GPIO4_B6
- GPIO0_C7
sheet 14
- RTC
- GPIO0_B2
- GPIO0_B0
- RS232 PORT
- SD Card
- KLXES15AAA1 *7
sheet 15
- RS485-1
- RS485 PORT
- GPIO3_D3
- RS485-2
- CAN PORT
- GPIO1_A6
- CAN-1
- CAN-2
sheet 16
- DC IN : 12V
- SYSTEM Power SW And OCP
- 2A限流
- VCC3VS_SYS
- 3.3v 3A
- 1A限流
- FB 0.765V
- FAN
- EN:1.3V(TYP)
- UVLO:10.5V
- VCC5V0_SYS
- PWM11_IR_M2
- 5V 8A
- EN:1.3V(TYP)
- UVLO:10.5V
- Fix Hole
sheet 17
- Button
- DEBUG
- 短按开机   长按关机
- LED
- GPIO1_C6
- GPIO1_D2
- IR Receiver
